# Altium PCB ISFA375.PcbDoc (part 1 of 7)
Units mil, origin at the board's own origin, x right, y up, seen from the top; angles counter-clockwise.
Board outline 5615 x 5520 mil, 6 copper layers (Top_SL, GND, POWER, Signal_Layer, GND2, Bottom_SL), stack 60.472 mil thick; 494 components, 307 nets, 1648 pads, 755 vias.
Unrouted connection lines stored in the file: 315.
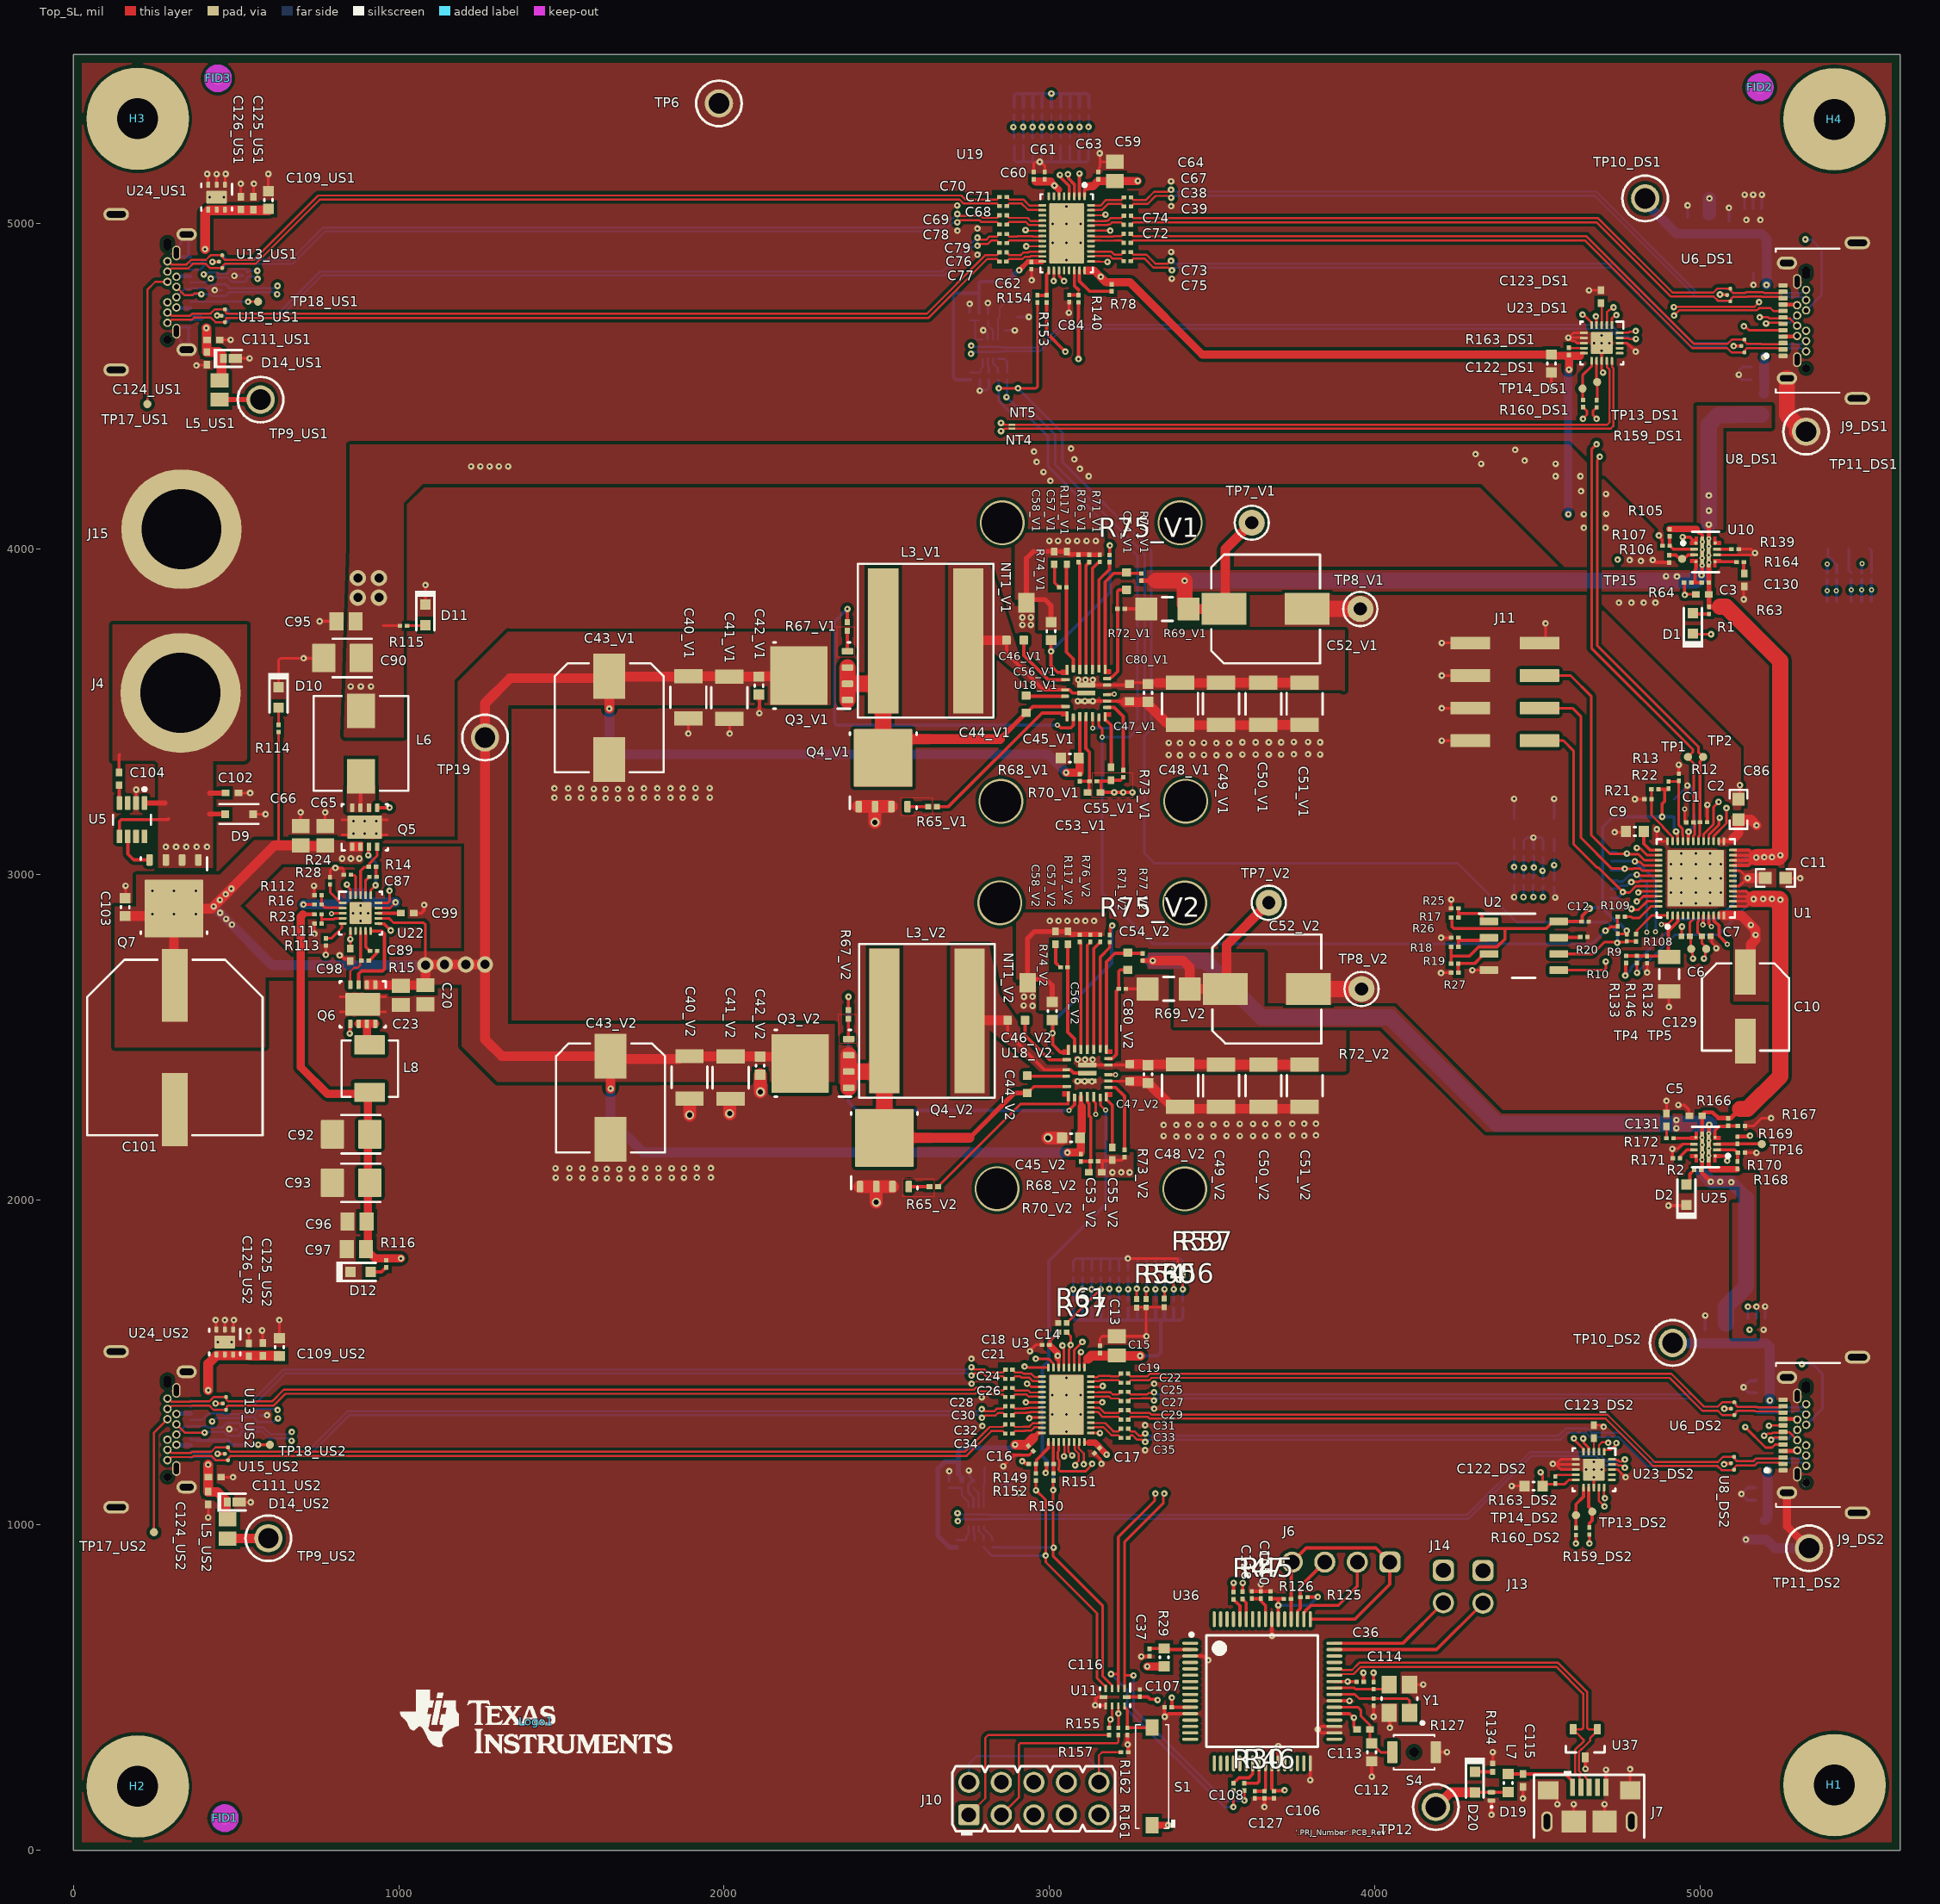
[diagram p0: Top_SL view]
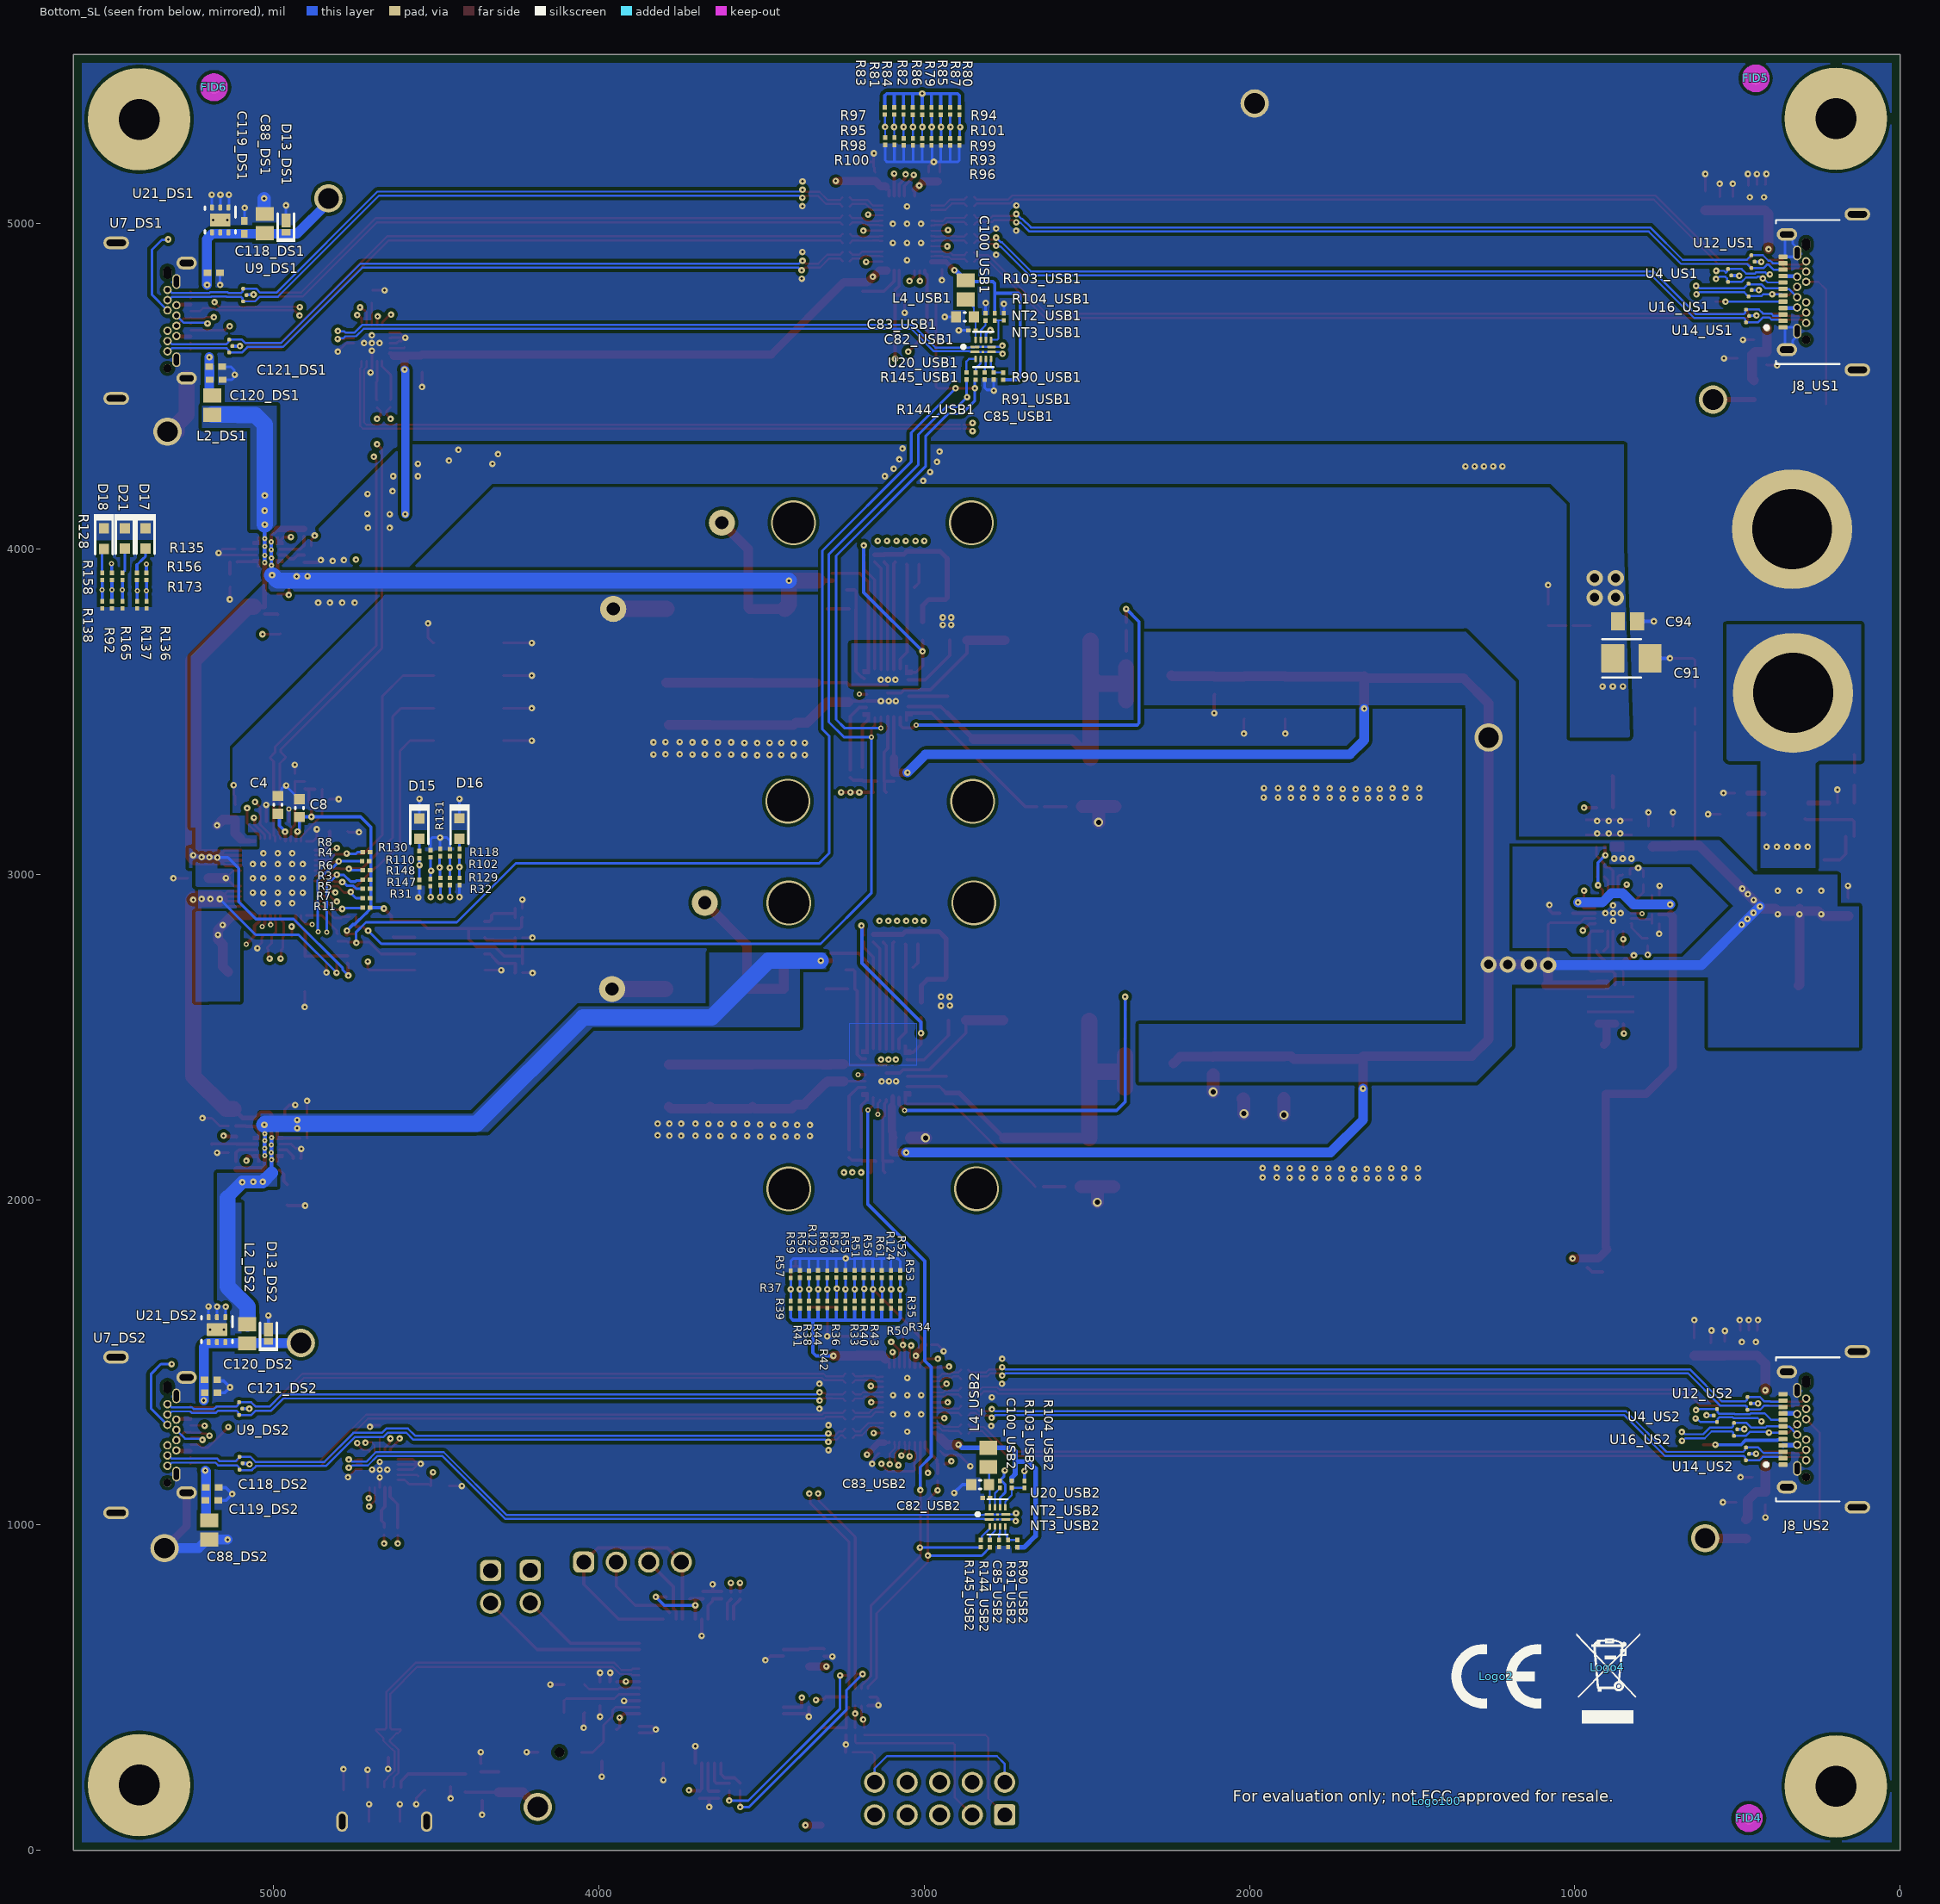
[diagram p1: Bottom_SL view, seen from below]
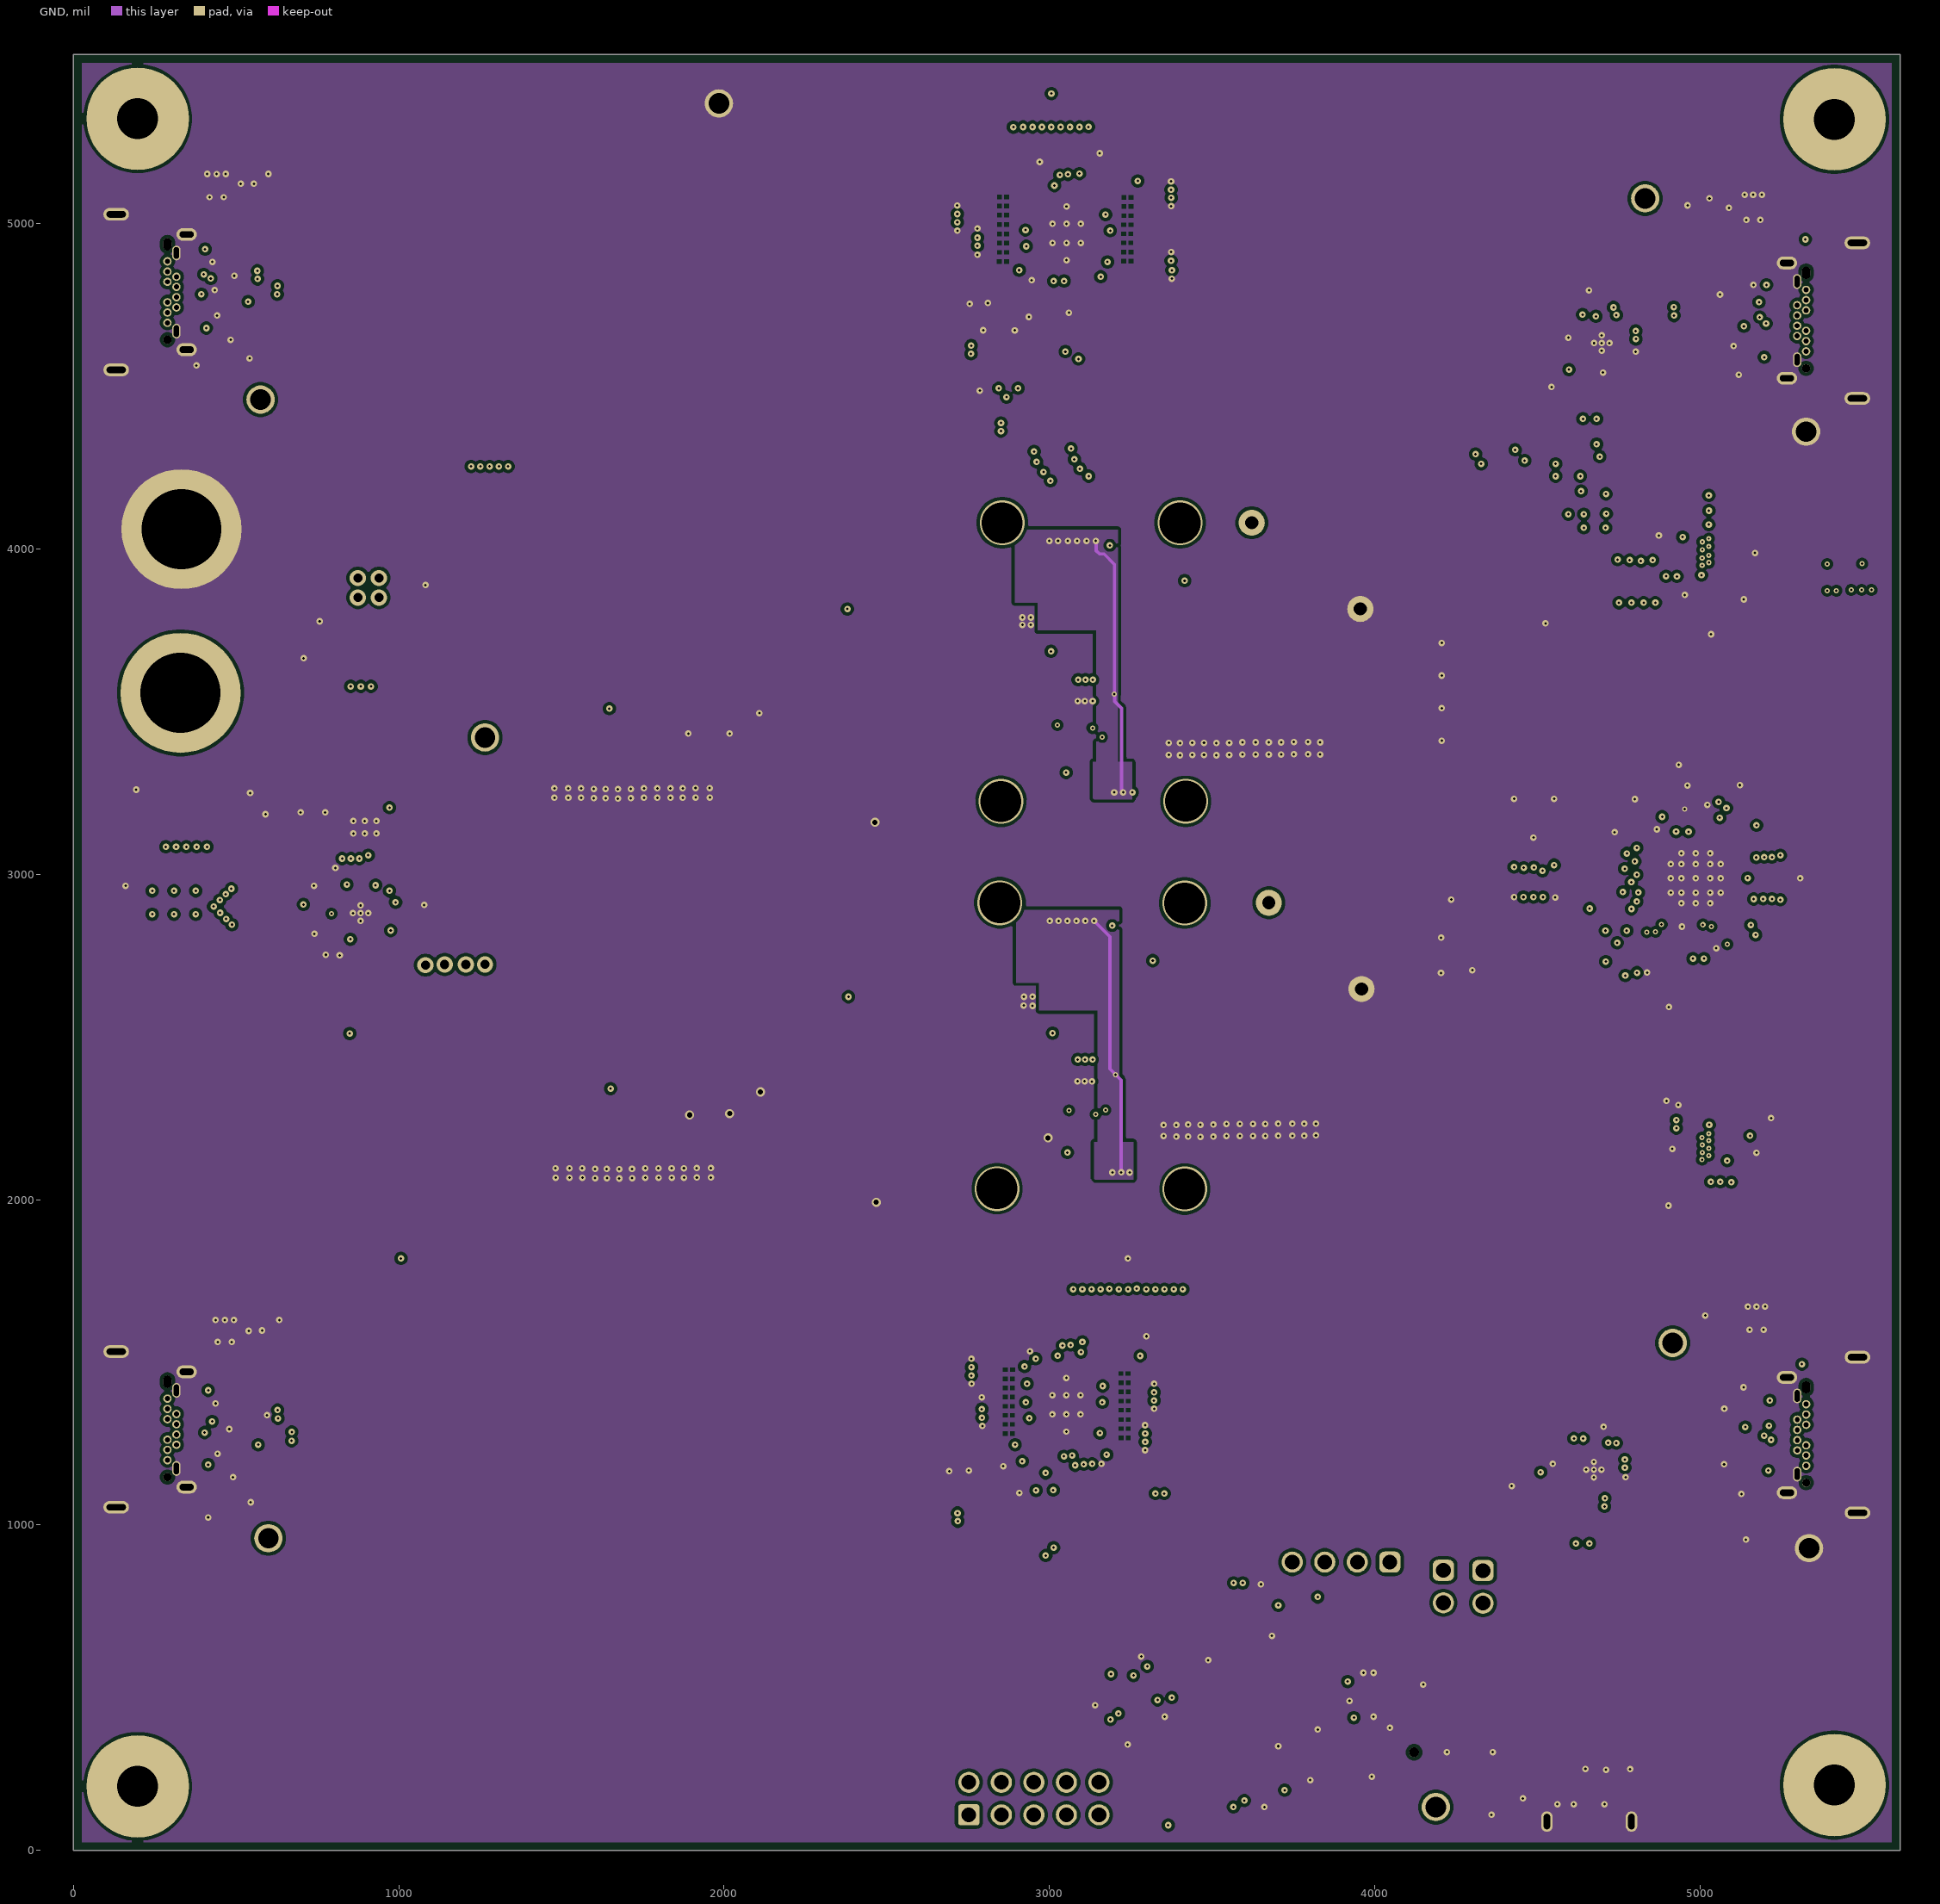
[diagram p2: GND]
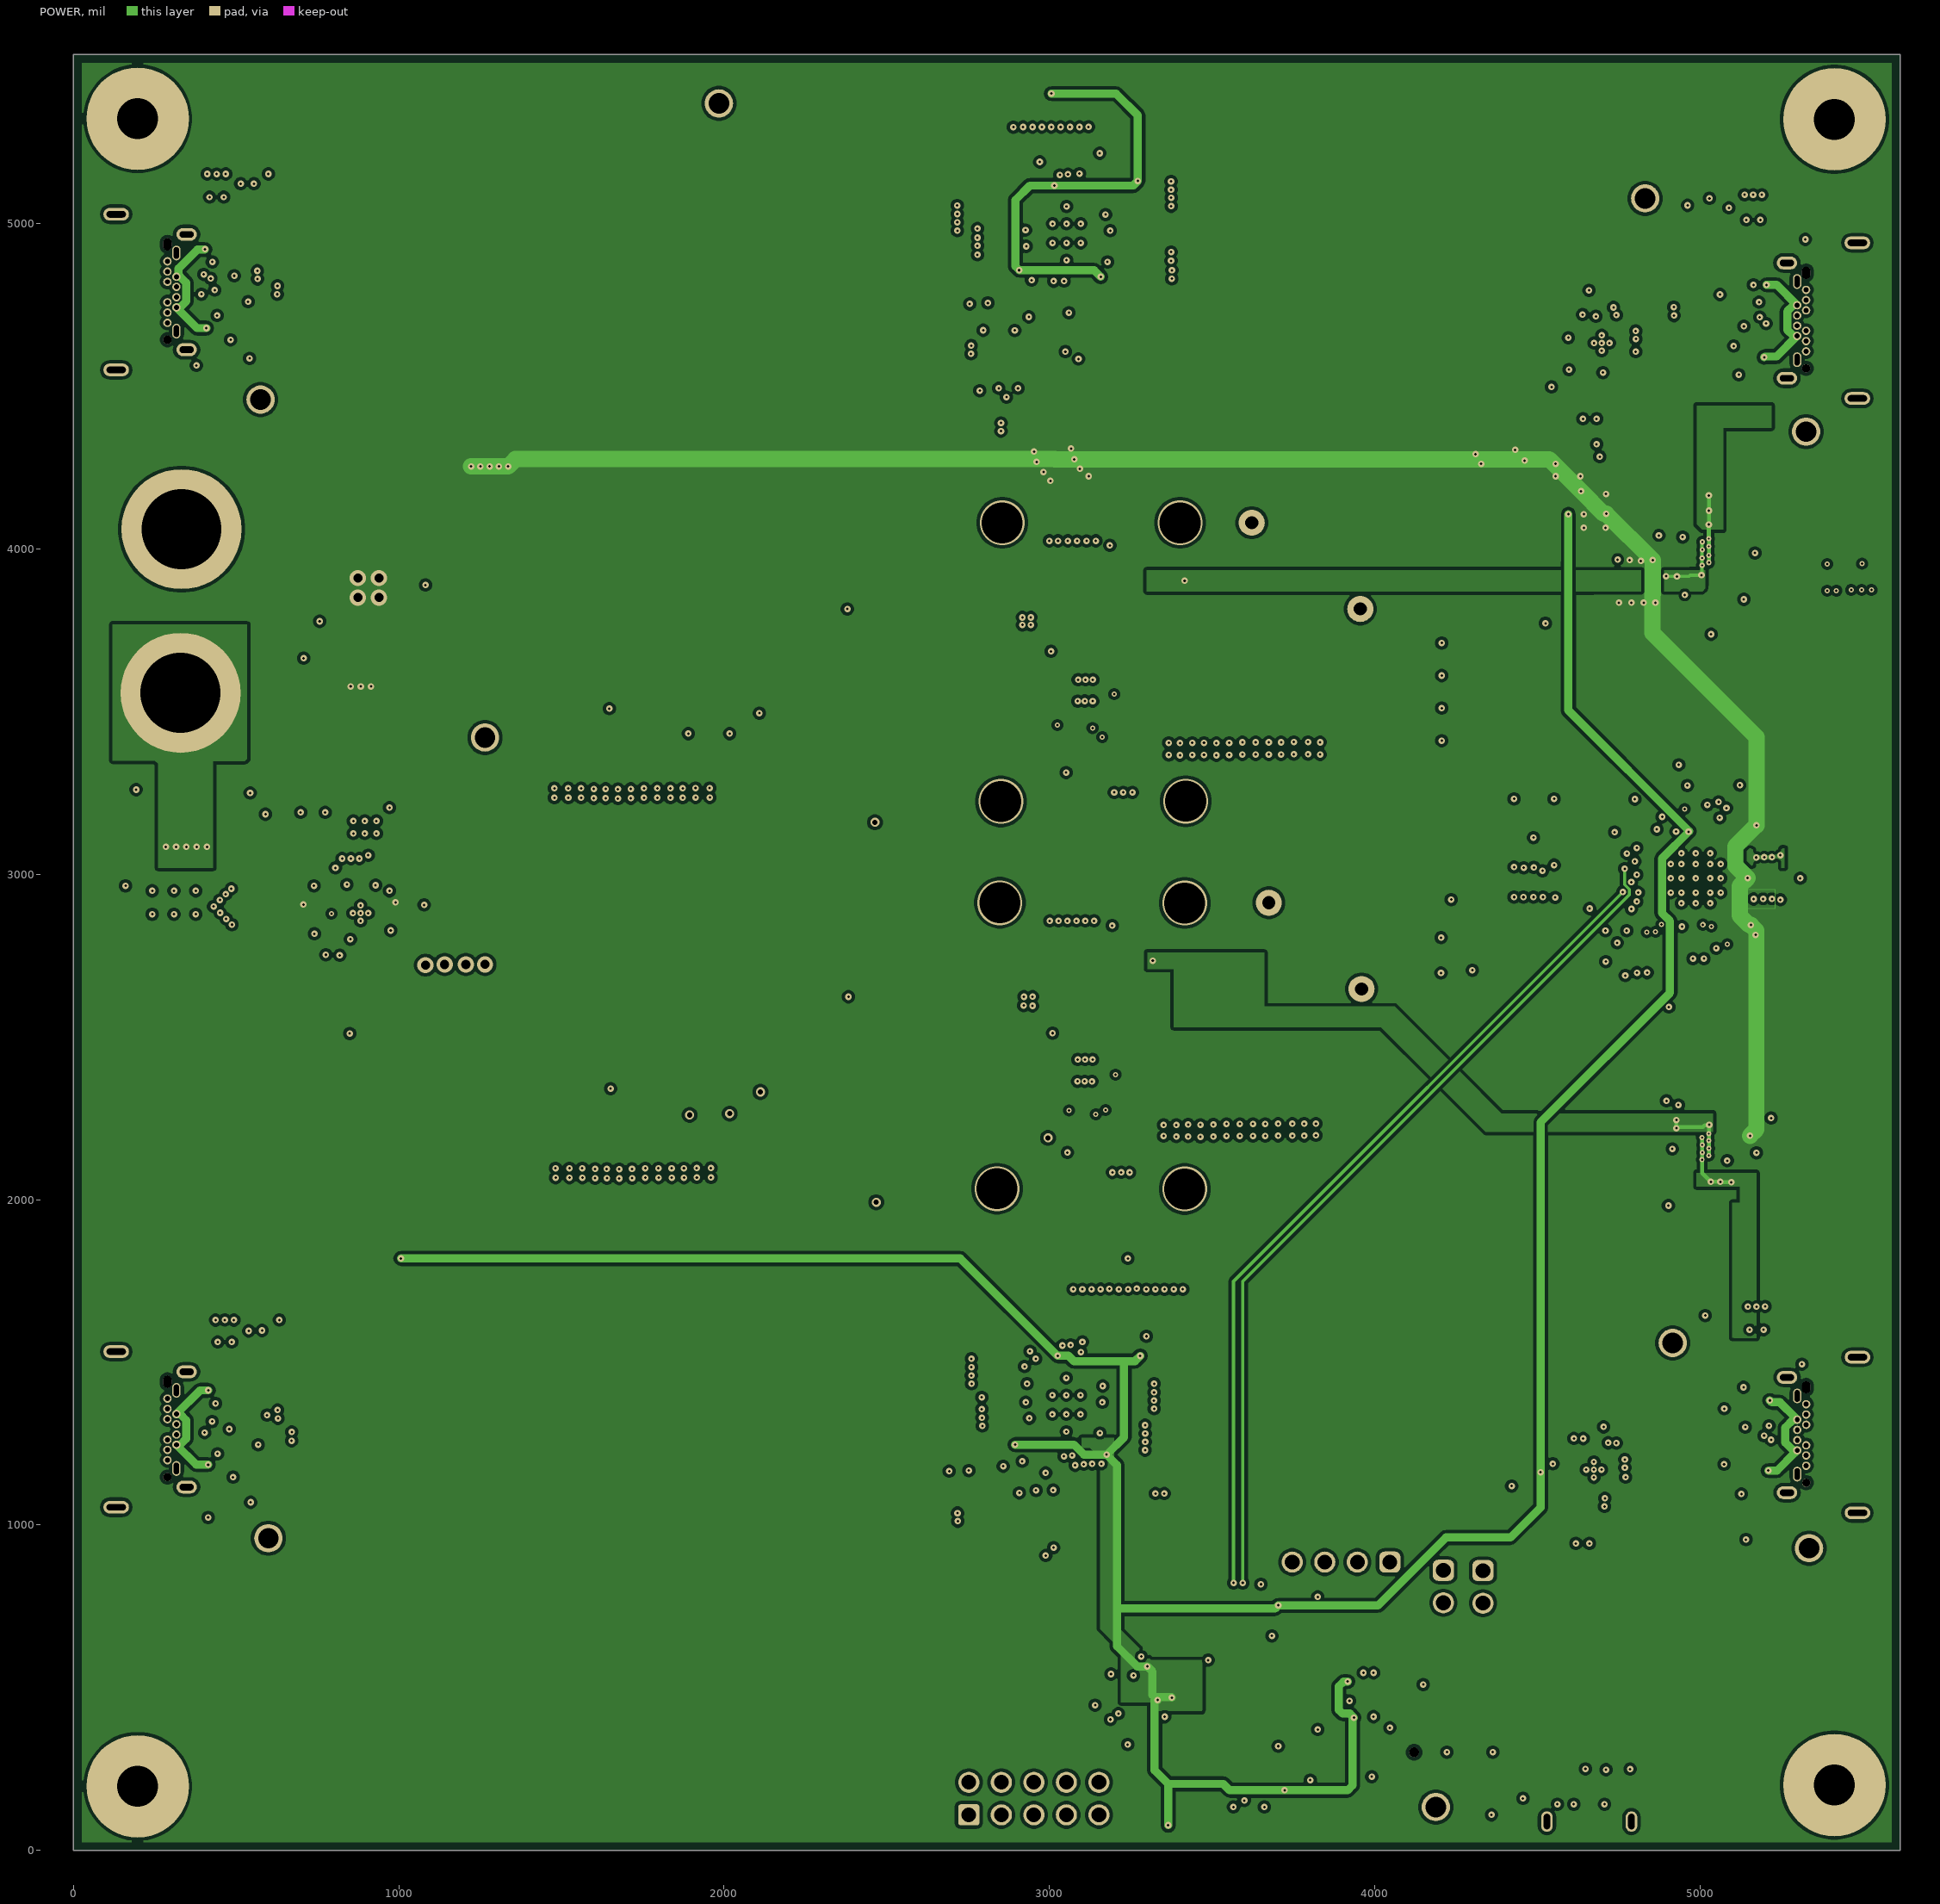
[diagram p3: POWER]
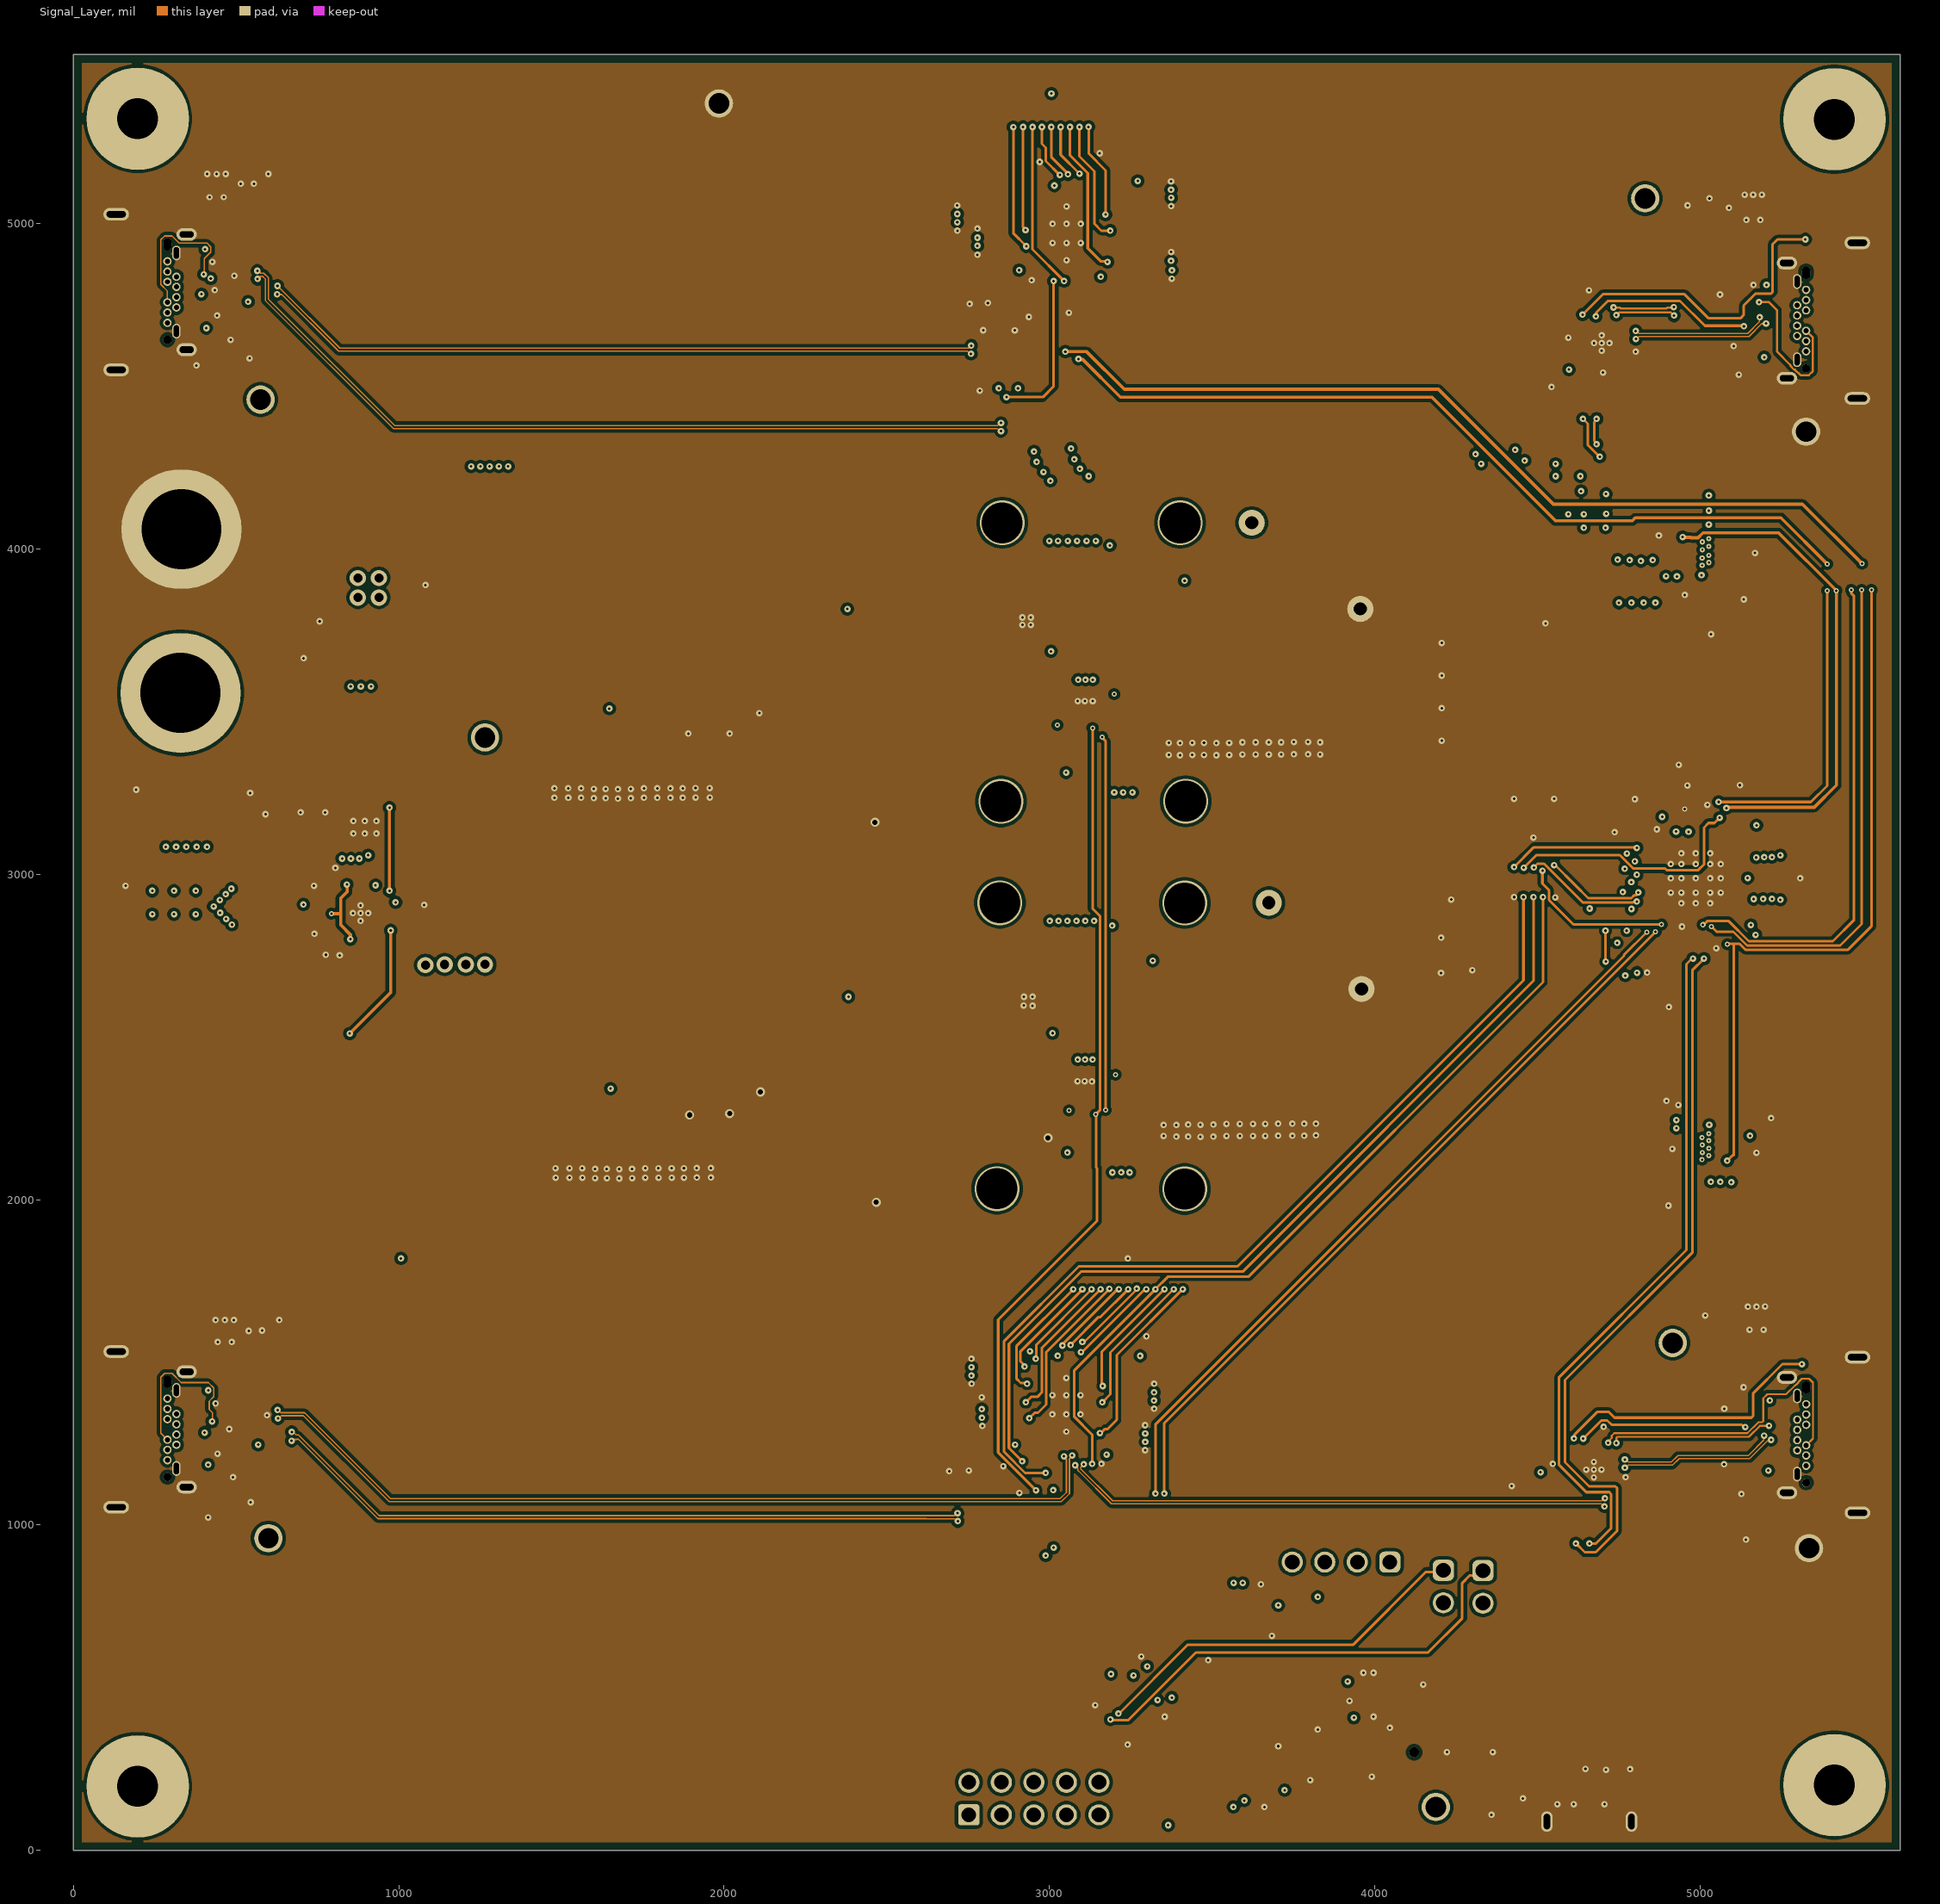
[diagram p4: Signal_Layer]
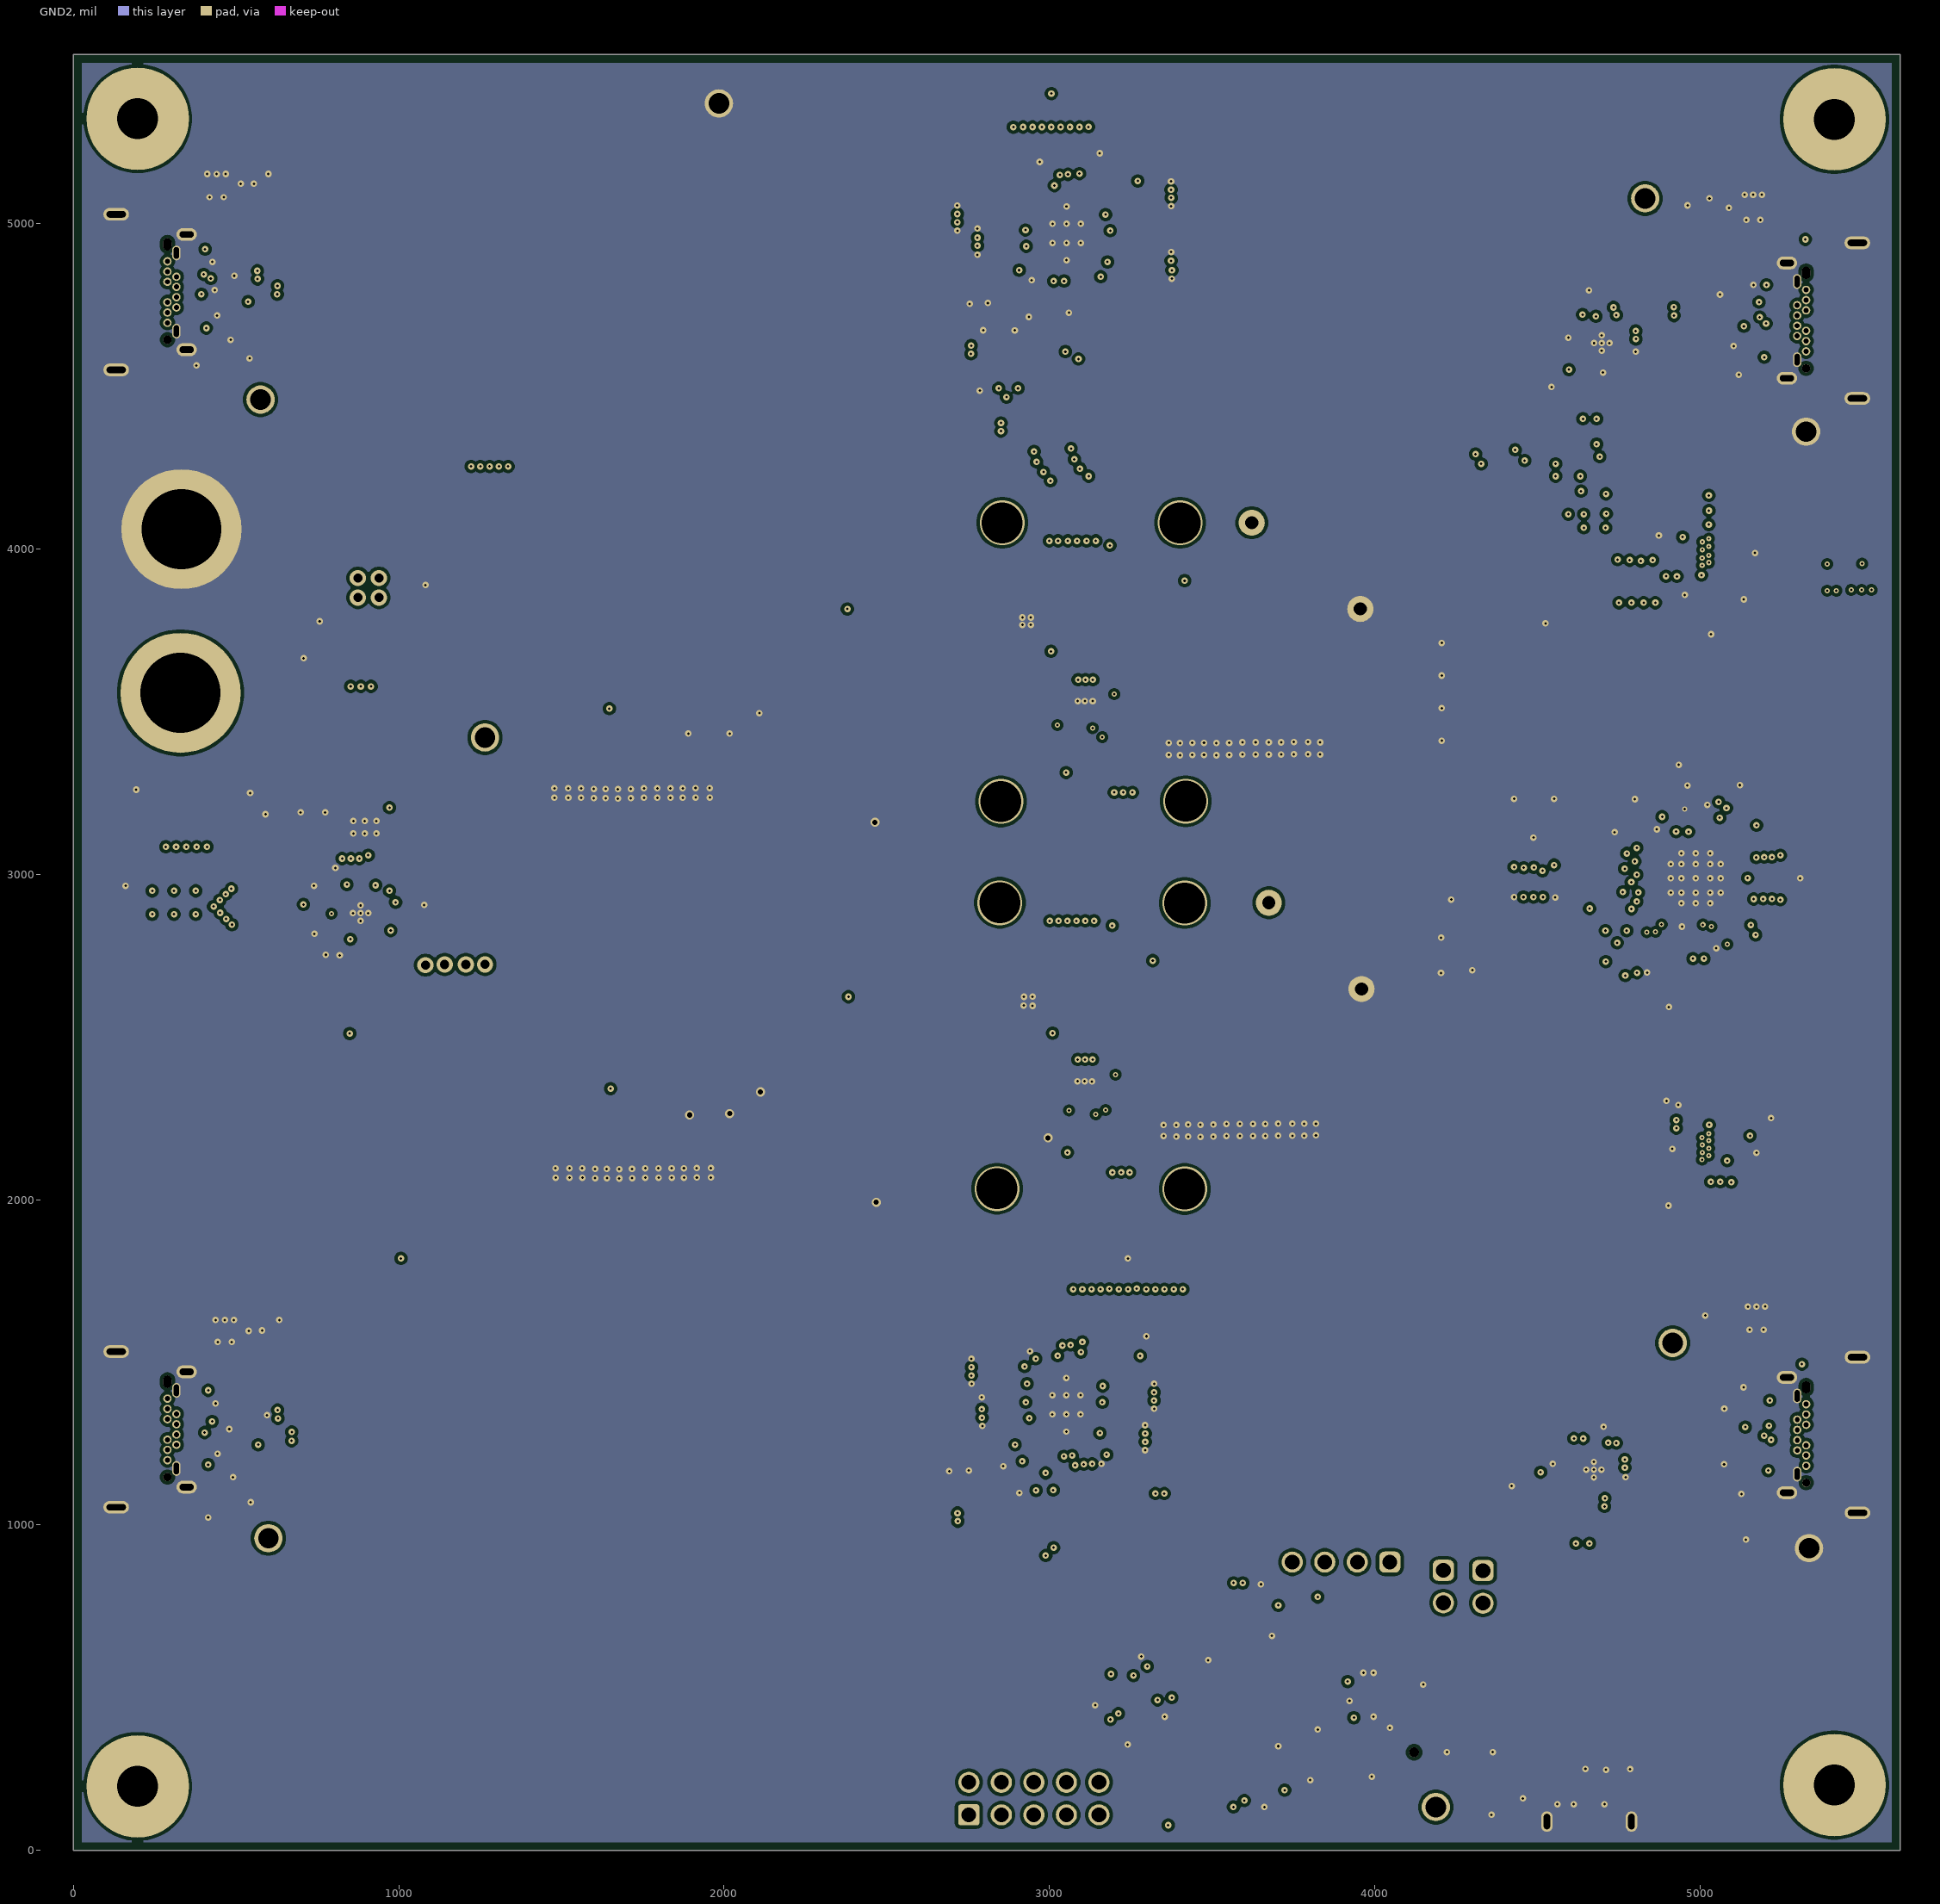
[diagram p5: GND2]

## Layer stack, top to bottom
Top Solder: solder mask 0.4, Solder Resist, Dk 3.5
Top_SL: signal copper 1.378
Dielectric 1: prepreg 5.669, FR-4, Dk 4.2
GND: signal copper 1.378
Dielectric 2: prepreg 16.929, FR-4, Dk 4.2
POWER: signal copper 1.378
Dielectric 3: core 7.008, FR-4, Dk 4.2
Signal_Layer: signal copper 1.378
Dielectric 4: prepreg 16.929, FR-4, Dk 4.2
GND2: signal copper 1.378
Dielectric 5: prepreg 5.669, FR-4, Dk 4.2
Bottom_SL: signal copper 1.378
Bottom Solder: solder mask 0.4, Solder Resist, Dk 3.5

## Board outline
0,0 5615,0 5615,5520 0,5520

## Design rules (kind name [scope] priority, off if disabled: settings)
AcuteAngle [All] p1: minimum=4.50000000000000E+0001 checktracksonly=FALSE
AssemblyTestPointUsage [All] p1: valid=2
BoardOutlineClearance BoardOutlineClearance_MountingHoles [OnCopper and InComponentClass('Mounting Holes')] p1: gap=39.37 ignorepadtopadclearanceinfootprint=FALSE
BoardOutlineClearance BoardOutlineClearance_Poly [OnCopper and IsPoly] p2: gap=25 ignorepadtopadclearanceinfootprint=FALSE
BoardOutlineClearance [OnCopper and Not InComponentClass('Logo') and not InComponentClass('FiducialMark') and not InRegion(1000,500,4000,800) and not InPoly] p3: gap=40 ignorepadtopadclearanceinfootprint=FALSE
Clearance Clearance_NetTie_1 [InNet('AUX_US1_*') vs InNet('AUX_DS1_*')] p1: gap=0 ignorepadtopadclearanceinfootprint=TRUE
Clearance Clearance_NetTie2 [InNet('D_US*') vs InNet('D1_D*')] p2: gap=0 ignorepadtopadclearanceinfootprint=TRUE
Clearance Clearance_Keepouts [((IsTrack Or IsArc) And Not InPoly) And IsFree and IsKeepOut vs ((IsTrack Or IsArc) And Not InPoly) And IsFree and IsKeepOut] p3: gap=0 ignorepadtopadclearanceinfootprint=FALSE
Clearance Clearance_Poly [InPolygon] p4: gap=10 ignorepadtopadclearanceinfootprint=TRUE
Clearance Clearance_FiducialMark [IsKeepOut and InComponentClass('FiducialMark') vs IsPad and InComponentClass('FiducialMark')] p5: gap=0 ignorepadtopadclearanceinfootprint=FALSE
Clearance [All] p6: gap=5 ignorepadtopadclearanceinfootprint=TRUE
ComponentClearance ComponentClearance_MountingHoles_FiducialMarks [InComponentClass('Mounting Holes') vs InComponentClass('FiducialMark')] p1: gap=50 collisioncheckmode=3 verticalgap=10 showdistances=FALSE
ComponentClearance ComponentClearance_Shunt [InComponentClass('Header') vs InComponentClass('Shunt')] p2: gap=0 collisioncheckmode=3 verticalgap=0 showdistances=FALSE
ComponentClearance ComponentClearance_Logo [InComponentClass('Logo')] p3: gap=30 collisioncheckmode=3 verticalgap=10 showdistances=FALSE
ComponentClearance ComponentClearance_ScrewToNut [(HasFootprint('NY PMS 440 0025 PH')) vs (HasFootprint('Keystone_1902C'))] p4: gap=5 collisioncheckmode=3 verticalgap=10 showdistances=FALSE
ComponentClearance ComponentClearance_MountingHoles [InComponentClass('Mounting Holes')] p5: gap=100 collisioncheckmode=3 verticalgap=100000 showdistances=FALSE
ComponentClearance ComponentClearance_NetTie [InComponent('NT*')] p6: gap=4 collisioncheckmode=3 verticalgap=0 showdistances=FALSE
ComponentClearance ComponentClearance_SmallPassives [HasFootprint('0201*') or HasFootprint('0402*') or HasFootprint('0508') or HasFootprint('0603*') or HasFootprint('0612') or HasFootprint('0805*') or HasFootprint('0815*') or HasFootprint('0830*') or HasFootprint('1206*') or HasFootprint('1210*') or HasFootprint('1808*') or HasFootprint('1812*') or HasFootprint('1825*') or HasFootprint('2010*') or HasFootprint('2220*') or HasFootprint('2225*') or HasFootprint('2512*') or HasFootprint('2728*') or HasFootprint('3518*') vs HasFootprint('0201*') or HasFootprint('0402*') or HasFootprint('0508') or HasFootprint('0603*') or HasFootprint('0612') or HasFootprint('0805*') or HasFootprint('0815*') or HasFootprint('0830*') or HasFootprint('1206*') or HasFootprint('1210*') or HasFootprint('1808*') or HasFootprint('1812*') or HasFootprint('1825*') or HasFootprint('2010*') or HasFootprint('2220*') or HasFootprint('2225*') or HasFootprint('2512*') or HasFootprint('2728*') or HasFootprint('3518*')] p7: gap=14.96 collisioncheckmode=3 verticalgap=10 showdistances=FALSE
ComponentClearance ComponentClearance_THtoSMT [IsThruComponent vs IsSMTComponent] p8: gap=30 collisioncheckmode=3 verticalgap=30 showdistances=FALSE
ComponentClearance ComponentClearance_THtoTH [IsThruComponent vs IsThruComponent] p9: gap=20 collisioncheckmode=3 verticalgap=30 showdistances=FALSE
ComponentClearance [All] p10: gap=20 collisioncheckmode=3 verticalgap=10 showdistances=FALSE
DiffPairsRouting DiffPairs_90Z [InNetClass('Diff_pairs')] p1: maxlimit=100 minlimit=5 mostfreqgap=5 toplayer_mingap=6 toplayer_maxgap=6 toplayer_prefgap=6 toplayer_minwidth=6.5 toplayer_maxwidth=6.5 toplayer_prefwidth=6.5 midlayer2_maxgap=5 midlayer2_minwidth=4.32 midlayer2_maxwidth=4.32 midlayer2_prefwidth=4.32 midlayer3_maxgap=5 midlayer3_minwidth=4.32 midlayer3_maxwidth=4.32 midlayer3_prefwidth=4.32 bottomlayer_mingap=6 bottomlayer_maxgap=6 bottomlayer_prefgap=6 bottomlayer_minwidth=6.5 bottomlayer_maxwidth=6.5 bottomlayer_prefwidth=6.5 impedanceprofiledriven=TRUE impedanceprofileid={51F6E1A3-C1B2-41CA-98E9-5ADEC133D8DC} impedanceprofilevalue=90.000000 maxuncoupledlength=1000
FabricationTestPointUsage TestPointUsage [All] p1: valid=2 allowmultiple=FALSE
FabricationTestpoint Testpoint [All] p1: side=3 testpointundercomponent=TRUE minsize=40 maxsize=100 preferedsize=60 minholesize=0 maxholesize=40 preferedholesize=32 testpointgrid=1 allowsidetop=TRUE allowsidebottom=TRUE usegrid=TRUE gridtolerance=0.01
FanoutControl Fanout_LCC [IsLCC] p1: bgadir=Out bgaviamode=Centered fanoutstyle=Auto fanoutdirection=Alternating viagrid=1 // Fanout_LCC (Default Rule)
FanoutControl Fanout_BGA [IsBGA] p2: bgadir=Out bgaviamode=Centered fanoutstyle=Auto fanoutdirection=Alternating viagrid=1 // Fanout_BGA (Default Rule)
FanoutControl Fanout_Default [All] p4: bgadir=Out bgaviamode=Centered fanoutstyle=Auto fanoutdirection=Alternating viagrid=1 // Fanout_Default (Default Rule)
FanoutControl Fanout_Small [(CompPinCount < 5)] p5: bgadir=Out bgaviamode=Centered fanoutstyle=Auto fanoutdirection=OutThenIn viagrid=1 // Fanout_Small (Default Rule)
HoleSize [All] p1: absolutevalues=TRUE maxlimit=251 minlimit=4 maxpercent=80.000 minpercent=20.000
HoleToHoleClearance [All] p1: gap=1 allowstackedmicrovias=TRUE
MinimumAnnularRing MinimumAnnularRing_ThermalPadVias [IsVia and InAnyComponent] p1: minimumring=3.94
MinimumAnnularRing [All] p2: minimumring=3.94
MinimumSolderMaskSliver MinimumSolderMaskSliver_Logo [InComponentClass('Logo') vs InComponentClass('Logo')] p1: minsoldermaskwidth=0.7
MinimumSolderMaskSliver [All] p2: minsoldermaskwidth=1
PlaneConnect [All] p1: planeconnectstyle=Relief reliefexpansion=10 reliefentries=4 reliefconductorwidth=10 reliefairgap=10
PolygonConnect [All] p1: connectstyle=Direct reliefconductorwidth=10 reliefentries=4 polygonreliefangle="90 Angle" airgapwidth=10
RoomDefinition DS1 [InComponentClass('DS1')] p1: confinementstyle=ConfineIn formatcopy=TRUE lockcomponents=FALSE outline 4507.83,5165 5647,5165 5647,4283.6 4507.83,4283.6
RoomDefinition US2 [InComponentClass('US2')] p2: confinementstyle=ConfineIn formatcopy=TRUE lockcomponents=FALSE outline 1010.1,872.35 -40,872.35 -40,1682.35 1010.1,1682.35
RoomDefinition US1 [InComponentClass('US1')] p3: confinementstyle=ConfineIn formatcopy=TRUE lockcomponents=FALSE outline 1010.1,4322.59 -40,4322.59 -40,5132.59 1010.1,5132.59
RoomDefinition USB2 [InComponentClass('USB2')] p4: confinementstyle=ConfineIn formatcopy=TRUE lockcomponents=FALSE outline 2881.87,1270.22 2881.87,864.2 2583.14,864.2 2583.14,1270.22
RoomDefinition V1 [InComponentClass('V1')] p5: confinementstyle=ConfineIn formatcopy=TRUE lockcomponents=FALSE outline 1434.13,4174.17 4016.44,4174.17 4016.44,3135.17 1434.13,3135.17
RoomDefinition V2 [InComponentClass('V2')] p6: confinementstyle=ConfineIn formatcopy=TRUE lockcomponents=FALSE outline 1437.91,3006.17 4020.23,3006.17 4020.23,1947 1437.91,1947
RoomDefinition USB1 [InComponentClass('USB1')] p7: confinementstyle=ConfineIn formatcopy=TRUE lockcomponents=FALSE outline 2951.5,4864.42 2951.5,4452.9 2627.14,4452.9 2627.14,4864.42
RoomDefinition DS2 [InComponentClass('DS2')] p8: confinementstyle=ConfineIn formatcopy=TRUE lockcomponents=FALSE outline 4413.93,1716 5660.62,1716 5660.62,844.66 4413.93,844.66
RoutingVias ThermalPadVias [IsVia and InAnyComponent] p1: holewidth=7.87 width=19.68 viastyle="Through Hole" minholewidth=4 minwidth=19.68 maxholewidth=12.99 maxwidth=23.62
RoutingVias [All] p2: holewidth=16 width=34 viastyle="Through Hole" minholewidth=4 minwidth=16 maxholewidth=40 maxwidth=65
SilkToBoardRegionClearance [Not ((IsComment or IsDesignator) And (Hide <> 'False')) and not InRegion(1000,500,4000,800)] p1:
SilkToSilkClearance SilkToSilkClearance_Pb-FreeLogo [(HasFootprint('Pb-Free_Overlay_Medium') OR HasFootprint('Pb-Free_Overlay_Small')) vs (HasFootprint('Pb-Free_Overlay_Medium') OR HasFootprint('Pb-Free_Overlay_Small'))] p1: silktosilkclearance=0
SilkToSilkClearance [All] p2: silktosilkclearance=0
SilkToSolderMaskClearance SilkToComponentPadClearance [(IsPad or IsFill or IsRegion) and InAnycomponent] p1: minsilkscreentomaskgap=2 clearancetoexposedcopper=TRUE
SilkToSolderMaskClearance "Silk to Solder Mask Opening" [All] p2: minsilkscreentomaskgap=2 clearancetoexposedcopper=FALSE
SolderMaskExpansion [All] p1: expansion=1.97 istentingtop=FALSE
UnRoutedNet [All] p1: checkbadconnections=TRUE
Width [All] p1: maxlimit=100 minlimit=6 preferedwidth=10 checkconnectedcopper=TRUE
Width vbus [InNetClass('vbus')] p2: maxlimit=100 minlimit=25 preferedwidth=30 checkconnectedcopper=TRUE
Width CC_GPIO [InNetClass('All Nets')] p3: maxlimit=100 minlimit=10 preferedwidth=15 checkconnectedcopper=TRUE
13 further rules are at their usual default settings.

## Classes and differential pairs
net class VCC_5V: VCC_5V
net class vbus: NetC47_V1_1 NetC47_V2_1 NetC109_US1_1 NetC109_US2_1 NetL5_US1_2 NetL5_US2_2 PA_PPHV PA_VBUS PB_PPHV PB_VBUS VBUS_DS1 VBUS_DS2
net class Diff_pairs: AUX_DS2_N AUX_DS2_P AUX_US1_N AUX_US1_P AUX_US2_N AUX_US2_P CRX1_N CRX1_P CRX2_N CRX2_P CTX1_N CTX1_P CTX2_N CTX2_P D1_D_N D1_D_P D1_D_USB2_N D1_D_USB2_P D1_RX1_N D1_RX1_P D1_RX2_N D1_RX2_P D1_TX1_N D1_TX1_P D1_TX2_N D1_TX2_P D2_RX1_N D2_RX1_P D2_RX2_N D2_RX2_P D2_TX1_N D2_TX1_P D2_TX2_N D2_TX2_P D_US1_N D_US1_P D_US2_N D_US2_P DRX1_N DRX1_P DRX2_N DRX2_P DTX1_N DTX1_P DTX2_N DTX2_P F_USB_D_N F_USB_D_P RX1_US1_N RX1_US1_P RX1_US2_N RX1_US2_P RX2_US1_N RX2_US1_P RX2_US2_N RX2_US2_P SSRX1_N SSRX1_P SSRX2_N SSRX2_P SSTX1_N SSTX1_P SSTX2_N SSTX2_P TX1_US1_N TX1_US1_P TX1_US2_N TX1_US2_P TX2_US1_N TX2_US1_P TX2_US2_N TX2_US2_P URX1_N URX1_P URX2_N URX2_P UTX1_N UTX1_P UTX2_N UTX2_P
channel class ISFA375_REDRIVER_TUSB216I: USB1 USB2
component class USB2: C82_USB2 C83_USB2 C85_USB2 C100_USB2 L4_USB2 NT2_USB2 NT3_USB2 R90_USB2 R91_USB2 R103_USB2 R104_USB2 R144_USB2 R145_USB2 U20_USB2
component class USB1: C82_USB1 C83_USB1 C85_USB1 C100_USB1 L4_USB1 NT2_USB1 NT3_USB1 R90_USB1 R91_USB1 R103_USB1 R104_USB1 R144_USB1 R145_USB1 U20_USB1
component class V2: C40_V2 C41_V2 C42_V2 C43_V2 C44_V2 C45_V2 C46_V2 C47_V2 C48_V2 C49_V2 C50_V2 C51_V2 C52_V2 C53_V2 C54_V2 C55_V2 C56_V2 C57_V2 C58_V2 C80_V2 L3_V2 NT1_V2 Q3_V2 Q4_V2 R65_V2 R67_V2 R68_V2 R69_V2 R70_V2 R71_V2 R72_V2 R73_V2 R74_V2 R75_V2 R76_V2 R77_V2 R117_V2 TP7_V2 TP8_V2 U18_V2
component class V1: C40_V1 C41_V1 C42_V1 C43_V1 C44_V1 C45_V1 C46_V1 C47_V1 C48_V1 C49_V1 C50_V1 C51_V1 C52_V1 C53_V1 C54_V1 C55_V1 C56_V1 C57_V1 C58_V1 C80_V1 L3_V1 NT1_V1 Q3_V1 Q4_V1 R65_V1 R67_V1 R68_V1 R69_V1 R70_V1 R71_V1 R72_V1 R73_V1 R74_V1 R75_V1 R76_V1 R77_V1 R117_V1 TP7_V1 TP8_V1 U18_V1
component class US1: C109_US1 C111_US1 C124_US1 C125_US1 C126_US1 D14_US1 J8_US1 L5_US1 TP9_US1 TP17_US1 TP18_US1 U4_US1 U12_US1 U13_US1 U14_US1 U15_US1 U16_US1 U24_US1
component class DS2: C88_DS2 C118_DS2 C119_DS2 C120_DS2 C121_DS2 C122_DS2 C123_DS2 D13_DS2 J9_DS2 L2_DS2 R159_DS2 R160_DS2 R163_DS2 TP10_DS2 TP11_DS2 TP13_DS2 TP14_DS2 U6_DS2 U7_DS2 U8_DS2 U9_DS2 U21_DS2 U23_DS2
channel class ISFA375_US_USB-C_CONN: US1 US2 US-1 US-2
component class "Sideband Interface": .Layer_Name J11
component class "Mounting Holes": .Layer_Name H1 H2 H3 H4
component class Logo: .Layer_Name Logo1
component class Hardware: !PCB .Layer_Name FID1 FID2 FID3 FID4 FID5 FID6 H1 H2 H3 H4 Logo1 Logo2 Logo4 Logo100
component class FiducialMark: .Layer_Name FID1 FID2 FID3 FID4 FID5 FID6
channel class ISFA375_DS_USB-C_CONN: DS1 DS2
channel class ISFA375_BUS_POWER_TPS55288: V1 V2 VBUS1 VBUS2
component class "TUSB1104 Redriver": .Layer_Name C38 C39 C59 C60 C61 C62 C63 C64 C67 C68 C69 C70 C71 C72 C73 C74 C75 C76 C77 C78 C79 C84 NT4 NT5 R78 R79 R80 R81 R82 R83 R84 R85 R86 R87 R93 R94 R95 R96 R97 R98 R99 R100 R101 R140 R153 R154 U19
component class "TUSB1044 Redriver": .Layer_Name C13 C14 C15 C16 C17 C18 C19 C21 C22 C24 C25 C26 C27 C28 C29 C30 C31 C32 C33 C34 C35 R33 R34 R35 R36 R37 R38 R39 R40 R41 R42 R43 R44 R50 R51 R52 R53 R54 R55 R56 R57 R58 R59 R60 R61 R123 R124 R149 R150 R151 R152 U3
component class "TPS65994 PD Controller": .Layer_Name C1 C2 C3 C4 C5 C6 C7 C8 C9 C10 C11 C12 C86 C129 C130 C131 D1 D2 D15 D16 D17 D18 D21 R1 R2 R3 R4 R5 R6 R7 R8 R9 R10 R11 R12 R13 R17 R18 R19 R20 R21 R22 R25 R26 R27 R31 R32 R63 R64 R92 R102 R105 R106 R107 R108 R109 R110 R118 R128 R129 R130 R131 R132 R133 R135 R136 R137 R138 R139 R146 R147 R148 R156 R158 R164 R165 R166 R167 R168 R169 R170 R171 R172 R173 TP1 TP2 TP4 TP5 TP15 TP16 U1 U2 U10 U25
component class US2: .Layer_Name C109_US2 C111_US2 C124_US2 C125_US2 C126_US2 D14_US2 J8_US2 L5_US2 TP9_US2 TP17_US2 TP18_US2 U4_US2 U12_US2 U13_US2 U14_US2 U15_US2 U16_US2 U24_US2
component class DS1: .Layer_Name C88_DS1 C118_DS1 C119_DS1 C120_DS1 C121_DS1 C122_DS1 C123_DS1 D13_DS1 J9_DS1 L2_DS1 R159_DS1 R160_DS1 R163_DS1 TP10_DS1 TP11_DS1 TP13_DS1 TP14_DS1 U6_DS1 U7_DS1 U8_DS1 U9_DS1 U21_DS1 U23_DS1
component class "MCU Debug Interface": .Layer_Name C36 C37 C105 C106 C107 C108 C110 C112 C113 C114 C115 C116 C127 C128 D19 D20 J6 J7 J10 J13 J14 L7 R29 R30 R45 R46 R47 R125 R126 R127 R134 R155 R157 R161 R162 S1 S4 TP12 U11 U36 U37 Y1
component class "Input Power Supply": .Layer_Name C20 C23 C65 C66 C87 C89 C90 C91 C92 C93 C94 C95 C96 C97 C98 C99 C101 C102 C103 C104 D9 D10 D11 D12 J4 J15 L6 L8 Q5 Q6 Q7 R14 R15 R16 R23 R24 R28 R111 R112 R113 R114 R115 R116 TP6 TP19 U5 U22
component class Header: .Layer_Name J6 J10 J11 J13 J14
differential pair F_USB_D: +F_USB_D_P -F_USB_D_N
differential pair D_US2: +D_US2_P -D_US2_N
differential pair D_US1: +D_US1_P -D_US1_N
differential pair UTX2: +UTX2_P -UTX2_N
differential pair UTX1: +UTX1_P -UTX1_N
differential pair URX2: +URX2_P -URX2_N
differential pair URX1: +URX1_P -URX1_N
differential pair SSTX2: +SSTX2_P -SSTX2_N
differential pair SSTX1: +SSTX1_P -SSTX1_N
differential pair SSRX2: +SSRX2_P -SSRX2_N
differential pair SSRX1: +SSRX1_P -SSRX1_N
differential pair DTX2: +DTX2_P -DTX2_N
differential pair DTX1: +DTX1_P -DTX1_N
differential pair DRX2: +DRX2_P -DRX2_N
differential pair DRX1: +DRX1_P -DRX1_N
differential pair CTX2: +CTX2_P -CTX2_N
differential pair CTX1: +CTX1_P -CTX1_N
differential pair CRX2: +CRX2_P -CRX2_N
differential pair CRX1: +CRX1_P -CRX1_N
differential pair D1_D_USB2: +D1_D_USB2_P -D1_D_USB2_N
differential pair TX2_US2: +TX2_US2_P -TX2_US2_N
differential pair TX2_US1: +TX2_US1_P -TX2_US1_N
differential pair TX1_US2: +TX1_US2_P -TX1_US2_N
differential pair TX1_US1: +TX1_US1_P -TX1_US1_N
differential pair RX2_US2: +RX2_US2_P -RX2_US2_N
differential pair RX2_US1: +RX2_US1_P -RX2_US1_N
differential pair RX1_US2: +RX1_US2_P -RX1_US2_N
differential pair RX1_US1: +RX1_US1_P -RX1_US1_N
differential pair C_AUX_DS2: +C_AUX_DS2_P -C_AUX_DS2_N
differential pair AUX_US1: +AUX_US1_P -AUX_US1_N
differential pair AUX_DS2: +AUX_DS2_P -AUX_DS2_N
differential pair C_AUX_DS1: +C_AUX_DS1_P -C_AUX_DS1_N
differential pair D2_TX1: +D2_TX1_P -D2_TX1_N
differential pair D1_TX1: +D1_TX1_P -D1_TX1_N
differential pair AUX_US2: +AUX_US2_P -AUX_US2_N
differential pair AUX_DS1: +AUX_DS1_P -AUX_DS1_N
differential pair D1_D: +D1_D_P -D1_D_N
differential pair D2_RX2: +D2_RX2_P -D2_RX2_N
differential pair D2_TX2: +D2_TX2_P -D2_TX2_N
differential pair D2_RX1: +D2_RX1_P -D2_RX1_N
differential pair D1_TX2: +D1_TX2_P -D1_TX2_N
differential pair D1_RX2: +D1_RX2_P -D1_RX2_N
differential pair D1_RX1: +D1_RX1_P -D1_RX1_N

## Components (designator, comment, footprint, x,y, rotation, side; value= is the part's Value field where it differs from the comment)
C1 "CGA1A2X7R1H221K030BA" 0201_033L 4969,3160 r0 top value=220pF
C2 "CGA1A2X7R1H221K030BA" 0201_033L 5010.89,3160.63 r180 top value=220pF
C3 "GRM155R6YA105KE11D" 0402L 5007.54,3861 r180 top value=1uF
C4 "GRM188R61E106MA73D" 0603L 4987,3213.78 r90 bottom value=10uF
C5 "GRM155R6YA105KE11D" 0402L 4986.77,2258.13 r180 top value=1uF
C6 "CGA1A2X7R1H221K030BA" 0201_033 4956.01,2810 r180 top value=220pF
C7 "CGA1A2X7R1H221K030BA" 0201_033 5019,2810 r0 top value=220pF
C8 "GRM188R61E106MA73D" 0603L 4920.5,3204 r270 bottom value=10uF
C9 "GRM188R61E106MA73D" 0603L 4799.9,3132.03 r0 top value=10uF
C10 "APXE100ARA121MF61G" CAPSMT_62_F61 5138.69,2594.59 r270 top value=120uF
C11 "GRM188R61E106MA73D" 0603 5231.86,2988.87 r0 top value=10uF
C12 "GRM033C71C104KE14D" 0201_033L 4646.9,2855.09 r0 top value=0.1uF
C13 "CL21B106KOQNNNE" 0805L 3207.1,1550.69 r90 top value=10uF
C14 "GRM033R61A104KE84D" 0201_033L 2988.72,1553.84 r180 top value=0.1uF
C15 "GRM033R61A104KE84D" 0201_033L 3155.61,1539.67 r90 top value=0.1uF
C16 "GRM033R61A104KE84D" 0201_033L 2943,1235.43 r315 top value=0.1uF
C17 "GRM033R61A104KE84D" 0201_033L 3146.65,1229.08 r225 top value=0.1uF
C18 "C0603X5R1A334K030BC" 0201_033L 2875.65,1477.42 r180 top value=0.33uF
C19 "C0603X5R1A334K030BC" 0201_033L 3230.72,1465.61 r180 top value=0.33uF
C20 "C2012X5R1V226M125AC" 0805L 1081.61,2630.03 r270 top value=22uF
C21 "C0603X5R1A334K030BC" 0201_033L 2875.37,1449.36 r180 top value=0.33uF
C22 "C0603X5R1A334K030BC" 0201_033L 3231.09,1437.29 r180 top value=0.33uF
C23 "C2012X5R1V226M125AC" 0805L 1006.61,2628.03 r270 top value=22uF
C24 "LMK063BJ224MP-F" 0201_033L 2875.37,1421.36 r180 top value=0.22uF
C25 "LMK063BJ224MP-F" 0201_033L 3231.09,1409.29 r180 top value=0.22uF
C26 "LMK063BJ224MP-F" 0201_033L 2875.37,1393.36 r180 top value=0.22uF
C27 "LMK063BJ224MP-F" 0201_033L 3231.09,1381.29 r180 top value=0.22uF
C28 "LMK063BJ224MP-F" 0201_033L 2875.37,1365.36 r180 top value=0.22uF
C29 "LMK063BJ224MP-F" 0201_033L 3231.09,1353.29 r180 top value=0.22uF
C30 "LMK063BJ224MP-F" 0201_033L 2875.37,1337.36 r180 top value=0.22uF
C31 "LMK063BJ224MP-F" 0201_033L 3231.09,1324.29 r180 top value=0.22uF
C32 "C0603X5R1A334K030BC" 0201_033L 2875.37,1309.36 r180 top value=0.33uF
C33 "C0603X5R1A334K030BC" 0201_033L 3231.09,1296.29 r180 top value=0.33uF
C34 "C0603X5R1A334K030BC" 0201_033L 2875.37,1281.36 r180 top value=0.33uF
C35 "C0603X5R1A334K030BC" 0201_033L 3231.09,1267.69 r180 top value=0.33uF
C36 "GRM033Z71C104KE14D" 0201L 3955.42,518.32 r0 top value=0.1uF
C37 "GRM033Z71C104KE14D" 0201L 3307.64,608.17 r90 top value=0.1uF
C38 "C0603X5R1A334K030BC" 0201_033L 3239.94,5024.96 r180 top value=0.33uF
C39 "C0603X5R1A334K030BC" 0201_033L 3239.52,4996.92 r180 top value=0.33uF
C40_V1 "CGA6P1X7R1N106M250AC" 1210_280 1890.13,3544.17 r270 top value=10uF (schematic designator C40)
C40_V2 "CGA6P1X7R1N106M250AC" 1210_280 1893.91,2376.17 r270 top value=10uF (schematic designator C40)
C41_V1 "CGA6P1X7R1N106M250AC" 1210_280 2016.13,3543.17 r270 top value=10uF (schematic designator C41)
C41_V2 "CGA6P1X7R1N106M250AC" 1210_280 2019.91,2375.17 r270 top value=10uF (schematic designator C41)
C42_V1 "GRT188R61H105ME13D" 0603L 2107.13,3580.17 r270 top value=1uF (schematic designator C42)
C42_V2 "GRT188R61H105ME13D" 0603L 2110.91,2412.17 r270 top value=1uF (schematic designator C42)
C43_V1 "EEHZA1H680P" SM_RADIAL_8MM 1647.13,3481.17 r270 top value=68uF (schematic designator C43)
C43_V2 "EEHZA1H680P" SM_RADIAL_8MM 1650.91,2313.17 r270 top value=68uF (schematic designator C43)
C44_V1 "GCM188L81H104KA57D" FP-GCM188L81H104KA57D_0603-MFG 2928.2,3522.91 r270 top (schematic designator C44)
C44_V2 "GCM188L81H104KA57D" FP-GCM188L81H104KA57D_0603-MFG 2931.99,2354.91 r270 top (schematic designator C44)
C45_V1 "GRT188R61H105ME13D" 0603L 3062.6,3358.01 r180 top value=1uF (schematic designator C45)
C45_V2 "GRT188R61H105ME13D" 0603L 3066.39,2190.01 r180 top value=1uF (schematic designator C45)
C46_V1 "GCM188L81H104KA57D" FP-GCM188L81H104KA57D_0603-MFG 2894.74,3719.88 r180 top (schematic designator C46)
C46_V2 "GCM188L81H104KA57D" FP-GCM188L81H104KA57D_0603-MFG 2898.53,2551.88 r180 top (schematic designator C46)
C47_V1 "GRT188R61H105ME13D" 0603L 3303.15,3557.73 r270 top value=1uF (schematic designator C47)
C47_V2 "GRT188R61H105ME13D" 0603L 3303,2386 r270 top value=1uF (schematic designator C47)
C48_V1 "CGA6P1X7R1N106M250AC" 1210_280 3401.58,3524.63 r270 top value=10uF (schematic designator C48)
C48_V2 "CGA6P1X7R1N106M250AC" 1210_280 3401.64,2351.01 r270 top value=10uF (schematic designator C48)
C49_V1 "CGA6P1X7R1N106M250AC" 1210_280 3527.59,3524.36 r270 top value=10uF (schematic designator C49)
C49_V2 "CGA6P1X7R1N106M250AC" 1210_280 3527.65,2350.73 r270 top value=10uF (schematic designator C49)
C50_V1 "CGA6P1X7R1N106M250AC" 1210_280 3657.47,3524.25 r270 top value=10uF (schematic designator C50)
C50_V2 "CGA6P1X7R1N106M250AC" 1210_280 3657.53,2350.63 r270 top value=10uF (schematic designator C50)
C51_V1 "CGA6P1X7R1N106M250AC" 1210_280 3784.47,3524.25 r270 top value=10uF (schematic designator C51)
C51_V2 "CGA6P1X7R1N106M250AC" 1210_280 3784.53,2350.63 r270 top value=10uF (schematic designator C51)
C52_V1 "EEHZA1E221P" SM_RADIAL_8MM 3664.74,3815.9 r0 top value=220uF (schematic designator C52)
C52_V2 "EEHZA1E221P" SM_RADIAL_8MM 3668.53,2647.9 r0 top value=220uF (schematic designator C52)
C53_V1 "CGA2B3X7R1H104K050BB" 0402L 3137.13,3252.17 r0 top value=0.1uF (schematic designator C53)
C53_V2 "CGA2B3X7R1H104K050BB" 0402L 3140.91,2084.17 r0 top value=0.1uF (schematic designator C53)
C54_V1 "GCM188L81H104KA57D" FP-GCM188L81H104KA57D_0603-MFG 3237.29,3901.32 r90 top (schematic designator C54)
C54_V2 "GCM188L81H104KA57D" FP-GCM188L81H104KA57D_0603-MFG 3241.08,2733.32 r90 top (schematic designator C54)
C55_V1 "CGA2B3X7R1H103K050BB" 0402L 3189.63,3309.39 r90 top value=0.01uF (schematic designator C55)
C55_V2 "CGA2B3X7R1H103K050BB" 0402L 3193.42,2141.39 r90 top value=0.01uF (schematic designator C55)
C56_V1 "GRT188R61C475KE13D" 0603L 3004.92,3748 r90 top value=4.7uF (schematic designator C56)
C56_V2 "GRT188R61C475KE13D" 0603L 3008.71,2580 r90 top value=4.7uF (schematic designator C56)
C57_V1 "CGA2B2C0G1H101J050BA" 0402L 3053.74,3972.88 r90 top value=100pF (schematic designator C57)
C57_V2 "CGA2B2C0G1H101J050BA" 0402L 3057.53,2804.88 r90 top value=100pF (schematic designator C57)
C58_V1 "CGA2B2X7R1H472K050BA" 0402L 3014.74,3972.88 r90 top value=4700pF (schematic designator C58)
C58_V2 "CGA2B2X7R1H472K050BA" 0402L 3018.53,2804.88 r90 top value=4700pF (schematic designator C58)
C59 "CL21B106KOQNNNE" 0805L 3201.31,5161 r90 top value=10uF
C60 "GRM033R61A104KE84D" 0201_033L 2951.5,5147.69 r90 top value=0.1uF
C61 "GRM033R61A104KE84D" 0201_033L 2985.63,5147.69 r90 top value=0.1uF
C62 "GRM033R61A104KE84D" 0201_033L 2944.65,4871.7 r270 top value=0.1uF
C63 "GRM033R61A104KE84D" 0201_033L 3150.01,5147.69 r90 top value=0.1uF
C64 "LMK063BJ224MP-F" 0201_033L 3239.94,5080.96 r180 top value=0.22uF
C65 "C2012X5R1V226M125AC" 0805L 773.75,3118.82 r90 top value=22uF
C66 "C2012X5R1V226M125AC" 0805L 698.61,3118.82 r90 top value=22uF
C67 "LMK063BJ224MP-F" 0201_033L 3239.94,5052.96 r180 top value=0.22uF
C68 "C0603X5R1A334K030BC" 0201_033L 2857.61,5026.34 r180 top value=0.33uF
C69 "C0603X5R1A334K030BC" 0201_033L 2857.61,4997.34 r180 top value=0.33uF
C70 "LMK063BJ224MP-F" 0201_033L 2857.61,5082.34 r180 top value=0.22uF
C71 "LMK063BJ224MP-F" 0201_033L 2857.61,5054.34 r180 top value=0.22uF
C72 "LMK063BJ224MP-F" 0201_033L 3239.31,4941 r180 top value=0.22uF
C73 "C0603X5R1A334K030BC" 0201_033L 3239.52,4912.92 r180 top value=0.33uF
C74 "LMK063BJ224MP-F" 0201_033L 3239.28,4969 r180 top value=0.22uF
C75 "C0603X5R1A334K030BC" 0201_033L 3239.52,4884.92 r180 top value=0.33uF
C76 "C0603X5R1A334K030BC" 0201_033L 2857.55,4912.02 r180 top value=0.33uF
C77 "C0603X5R1A334K030BC" 0201_033L 2857.12,4883.51 r180 top value=0.33uF
C78 "LMK063BJ224MP-F" 0201_033L 2857.61,4968.48 r180 top value=0.22uF
C79 "LMK063BJ224MP-F" 0201_033L 2857.61,4940.34 r180 top value=0.22uF
C80_V1 "GCM188L81H104KA57D" FP-GCM188L81H104KA57D_0603-MFG 3246.21,3559 r90 top (schematic designator C80)
C80_V2 "GCM188L81H104KA57D" FP-GCM188L81H104KA57D_0603-MFG 3247,2390 r90 top (schematic designator C80)
C82_USB1 "GRM033R61A104KE84D" 0201_033L 2853,4672 r0 bottom value=0.1uF (schematic designator C82)
C82_USB2 "GRM033R61A104KE84D" 0201_033L 2809.01,1083.3 r0 bottom value=0.1uF (schematic designator C82)
C83_USB1 "C0603C105K4PACTU" 0603L 2874.55,4713.62 r0 bottom value=1uF (schematic designator C83)
C83_USB2 "C0603C105K4PACTU" 0603L 2828.09,1124.12 r0 bottom value=1uF (schematic designator C83)
C84 "C0603X5R1A334K030BC" 0201_033L 3060.84,4770.17 r90 top value=0.33uF
C85_USB1 "GRM033R61A104KE84D" 0201_033L 2814,4532 r270 bottom value=0.1uF (schematic designator C85)
C85_USB2 "GRM033R61A104KE84D" 0201_033L 2770.01,943.3 r270 bottom value=0.1uF (schematic designator C85)
C86 "GRM188R61E106MA73D" 0603 5118.69,3199.82 r90 top value=10uF
C87 "GRM033R61A104KE84D" 0201_033L 920.63,2992.6 r0 top value=0.1uF
C88_DS1 "CL21B106KOQNNNE" 0805L 5026.77,5000.4 r270 bottom value=10uF (schematic designator C88)
C88_DS2 "CL21B106KOQNNNE" 0805L 5197.95,985 r90 bottom value=10uF (schematic designator C88)
C89 "GRM033R61A104KE84D" 0201_033L 922.47,2764.69 r180 top value=0.1uF
C90 "T520B107M006ATE015" 3528-21 826.6,3665 r180 top value=100uF
C91 "T520B107M006ATE015" 3528-21 825.98,3664.38 r180 bottom value=100uF
C92 "T520B107M006ATE015" 3528-21 853.58,2201.03 r180 top value=100uF
C93 "T520B107M006ATE015" 3528-21 853.18,2052.03 r180 top value=100uF
C94 "GRM21BR61A476ME15L" 0805L 837.54,3778 r180 bottom value=47uF
C95 "GRM21BR61A476ME15L" 0805L 837.54,3778 r180 top value=47uF
C96 "GRM21BR61A476ME15L" 0805L 871.64,1933.03 r180 top value=47uF
C97 "GRM21BR61A476ME15L" 0805L 869.61,1848.03 r180 top value=47uF
C98 "GRM155R60J475ME47D" 0402L 850.57,2752.88 r270 top value=4.7uF
C99 "GRM155R60J475ME47D" 0402L 1026.29,2880.95 r0 top value=4.7uF
C100_USB1 "GRM033R61A104KE84D" 0201_033L 2811.27,4713.62 r90 bottom value=0.1uF (schematic designator C100)
C100_USB2 "GRM033R61A104KE84D" 0201_033L 2767.27,1124.93 r90 bottom value=0.1uF (schematic designator C100)
C101 "EEV-FK1J221Q" SM_RADIAL_H13 311.61,2468.09 r270 top value=220uF
C102 "GCM155R71H104KE02D" 0402L 487,3250 r0 top value=0.1uF
C103 "GRM188R6YA225KA12D" 0603L 158.92,2899.65 r90 top value=2.2uF
C104 "GRM155R6YA105KE11D" 0402L 140.22,3294 r270 top value=1uF
C105 "GRM033Z71C104KE14D" 0201L 3679.56,784.86 r90 top value=0.1uF
C106 "GRM033Z71C104KE14D" 0201L 3690.21,171.05 r270 top value=0.1uF
C107 "GRM033Z71C104KE14D" 0201L 3365.3,439.98 r180 top value=0.1uF
C108 "GRM033Z71C104KE14D" 0201L 3631.33,171.05 r270 top value=0.1uF
C109_US1 "GRM188R6YA475KE15D" 0603L 599,5073 r90 top value=4.7uF (schematic designator C109)
C109_US2 "GRM188R6YA475KE15D" 0603L 633,1547 r90 top value=4.7uF (schematic designator C109)
C110 "GRM033Z71C104KE14D" 0201L 3622,785 r90 top value=0.1uF
C111_US1 "C0402C103J5RACTU" 0402L 430,4643 r0 top value=0.01uF (schematic designator C111)
C111_US2 "C0402C103J5RACTU" 0402L 434,1147 r0 top value=0.01uF (schematic designator C111)
C112 "06035A181JAT2A" 0603L 3990.85,301.56 r270 top value=180pF
C113 "GJM0335C1E100JB01D" 0201L 3996.52,455.34 r270 top value=10pF
C114 "GJM0335C1E100JB01D" 0201L 3996.52,506.64 r90 top value=10pF
C115 "C0402C103J5RACTU" 0402L 4455.86,214.84 r90 top value=0.01uF
C116 "GRM033Z71C104KE14D" 0201L 3277.8,483.26 r90 top value=0.1uF
C118_DS1 "C0402C103J5RACTU" 0402L 5183.85,4848.92 r180 bottom value=0.01uF (schematic designator C118)
C118_DS2 "C0402C103J5RACTU" 0402L 5188.11,1115.2 r180 bottom value=0.01uF (schematic designator C118)
C119_DS1 "C0402C103J5RACTU" 0402L 5090.22,4988.58 r90 bottom value=0.01uF (schematic designator C119)
C119_DS2 "C0402C103J5RACTU" 0402L 5190,1076 r180 bottom value=0.01uF (schematic designator C119)
C120_DS1 "C0402C103J5RACTU" 0402L 5176.21,4520.5 r180 bottom value=0.01uF (schematic designator C120)
C120_DS2 "C0402C103J5RACTU" 0402L 5193,1446 r180 bottom value=0.01uF (schematic designator C120)
C121_DS1 "C0402C103J5RACTU" 0402L 5177.94,4560.51 r180 bottom value=0.01uF (schematic designator C121)
C121_DS2 "C0402C103J5RACTU" 0402L 5192,1407 r180 bottom value=0.01uF (schematic designator C121)
C122_DS1 "GRT188R61H105ME13D" 0603L 4543.49,4570.18 r270 top value=1uF (schematic designator C122)
C122_DS2 "GRT188R61H105ME13D" 0603L 4488.33,1119.81 r180 top value=1uF (schematic designator C122)
C123_DS1 "CGA2B3X7R1H104K050BB" 0402L 4696,4775.71 r270 top value=0.1uF (schematic designator C123)
C123_DS2 "CGA2B3X7R1H104K050BB" 0402L 4673.68,1287.26 r270 top value=0.1uF (schematic designator C123)
C124_US1 "C0402C103J5RACTU" 0402L 410.3,4586.13 r270 top value=0.01uF (schematic designator C124)
C124_US2 "C0402C103J5RACTU" 0402L 414.39,1083.3 r270 top value=0.01uF (schematic designator C124)
C125_US1 "C0402C103J5RACTU" 0402L 553,5063 r90 top value=0.01uF (schematic designator C125)
C125_US2 "C0402C103J5RACTU" 0402L 582,1540 r90 top value=0.01uF (schematic designator C125)
C126_US1 "C0402C103J5RACTU" 0402L 514,5063.64 r90 top value=0.01uF (schematic designator C126)
C126_US2 "C0402C103J5RACTU" 0402L 539,1539 r90 top value=0.01uF (schematic designator C126)
C127 "GRM035R60J475ME15D" 0201L 3660.86,171.05 r270 top value=4.7uF
C128 "GRM035R60J475ME15D" 0201L 3650.03,784.86 r90 top value=4.7uF
C129 "C3216JB1E476M160AC" 1206L 4904.75,2693.4 r90 top value=47uF
C130 "C0402C103J5RACTU" 0402L 5136.46,3904.7 r90 top value=0.01uF
C131 "C0402C103J5RACTU" 0402L 4897.17,2244.94 r270 top value=0.01uF
D1 "150060VS75000" WL-SMCW_GREEN 4978.29,3771.62 r90 top value=Green
D2 "150060VS75000" WL-SMCW_GREEN 4957.96,2015.39 r90 top value=Green
D9 "PESD24VL1BA,115" SOD-323-Bi 509,3185.39 r180 top value=24V
D10 "150060VS75000" WL-SMCW_GREEN 630,3543.96 r270 top value=Green
D11 "150060VS75000" WL-SMCW_GREEN 1082.02,3797.69 r270 top value=Green
D12 "150060VS75000" WL-SMCW_GREEN 882.47,1777.89 r0 top value=Green
D13_DS1 "NSR20F30NXT5G" DSN2_0603 4962,4999.17 r90 bottom value=30V (schematic designator D13)
D13_DS2 "NSR20F30NXT5G" DSN2_0603 5016,1590 r90 bottom value=30V (schematic designator D13)
D14_US1 "NSR20F30NXT5G" DSN2_0603 486,4586 r0 top value=30V (schematic designator D14)
D14_US2 "NSR20F30NXT5G" DSN2_0603 498,1071 r0 top value=30V (schematic designator D14)
D15 "150060VS75000" WL-SMCW_GREEN 4552,3140.77 r270 bottom value=Green
D16 "150060VS75000" WL-SMCW_GREEN 4428.35,3140.88 r270 bottom value=Green
D17 "150060VS75000" WL-SMCW_GREEN 5393.39,4032.77 r270 bottom value=Green
D18 "150060VS75000" WL-SMCW_GREEN 5521.25,4032.08 r270 bottom value=Green
D19 "TPD1E1B04DPYR" DPY0002A 4358.86,165.84 r90 top
D20 "150060VS75000" WL-SMCW_GREEN 4307.86,209.84 r270 top value=Green
D21 "150060VS75000" WL-SMCW_GREEN 5456.79,4032.59 r270 bottom value=Green
FID1 "Fiducial" Fiducial10-20 465,99 r90 top
FID2 "Fiducial" Fiducial10-20 5183.49,5419.29 r90 top
FID3 "Fiducial" Fiducial10-20 443.82,5447 r90 top
FID4 "Fiducial" Fiducial10-20 465,99 r90 bottom
FID5 "Fiducial" Fiducial10-20 443.82,5447 r90 bottom
FID6 "Fiducial" Fiducial10-20 5183.49,5419.29 r90 bottom
H1 "NY PMS 440 0025 PH" "NY PMS 440 0025 PH" 5412.9,201.06 r0 top
H2 "NY PMS 440 0025 PH" "NY PMS 440 0025 PH" 197,197 r0 top
H3 "NY PMS 440 0025 PH" "NY PMS 440 0025 PH" 197,5323 r0 top
H4 "NY PMS 440 0025 PH" "NY PMS 440 0025 PH" 5413,5321 r0 top
J4 "930 176-101" Hirschmann_930_176-101 329,3558 r270 top
J6 "61300411121" WURTH_61300411121 3896.52,886.12 r180 top
J7 "10118193-0001LF" FCI_10118193-0001LF 4659.32,31.46 r0 top
J8_US1 "632723130112" FP-632723130112_CONN_USB_9MM65_10MM0-MFG#1 180,4790 r90 bottom (schematic designator J8)
J8_US2 "632723130112" FP-632723130112_CONN_USB_9MM65_10MM0-MFG#2 180,1294 r90 bottom (schematic designator J8)
J9_DS1 "632723130112" FP-632723130112_CONN_USB_9MM65_10MM0-MFG#2 5434.83,4702.27 r90 top (schematic designator J9)
J9_DS2 "632723130112" FP-632723130112_CONN_USB_9MM65_10MM0-MFG#2 5435.17,1276.76 r90 top (schematic designator J9)
J10 "61301021121" WURTH_61301021121 2952.24,159.26 r0 top
J11 "61000821121" Wurth_61000821121 4400.15,3561.17 r180 top
J13 "61300211121" WURTH_61300211121 4332.85,809.86 r270 top
J14 "61300211121" WURTH_61300211121 4211.08,810.88 r270 top
J15 "930 176-100" Hirschmann_930_176-100 331.92,4061.16 r180 top
L2_DS1 "742792021" 0805L 5188.87,4442.24 r90 bottom value="22 ohm" (schematic designator L2)
L2_DS2 "742792021" 0805L 5081.11,1588 r270 bottom value="22 ohm" (schematic designator L2)
L3_V1 "XAL1010-472MEB" XAL1010 2619.74,3717.88 r0 top value=4.7uH (schematic designator L3)
L3_V2 "XAL1010-472MEB" XAL1010 2623.53,2549.88 r0 top value=4.7uH (schematic designator L3)
L4_USB1 "74279207" 0805L 2871.98,4796.8 r270 bottom value="100 ohm" (schematic designator L4)
L4_USB2 "74279207" 0805L 2803,1208 r270 bottom value="100 ohm" (schematic designator L4)
L5_US1 "742792021" 0805L 448.8,4489 r270 top value="22 ohm" (schematic designator L5)
L5_US2 "742792021" 0805L 473.7,988 r270 top value="22 ohm" (schematic designator L5)
L6 "744314330" WE-HCI_7050 883.65,3402.23 r270 top value=3.3uH
L7 "74279228260" 0603L 4410.17,207.08 r90 top value="26 ohm"
L8 "74437324022" WE-LHMI_4020 910.42,2403.03 r270 top value=2.2uH
Logo1 "Texas Instruments" TI_Stacked_Overlay_Small 1422,396 r0 top
Logo2 "CE Mark" CE_Mark_5mm 1241,535 r180 bottom
Logo4 "WEEE logo" WEEE_Minimum 899,563 r180 bottom
Logo100 "FCC disclaimer" FCC_disclaimer 1424.54,151 r180 bottom
NT1_V1 "Net-Tie" Net-Tie_50milWide_30milLong 2929.19,3835 r90 top net-tie (schematic designator NT1)
NT1_V2 "Net-Tie" Net-Tie_50milWide_30milLong 2932.98,2667 r90 top net-tie (schematic designator NT1)
NT2_USB1 "Net-Tie" Net-Tie_6x8mil 2819.08,4621.62 r180 bottom net-tie (schematic designator NT2)
NT2_USB2 "Net-Tie" Net-Tie_6x8mil 2774.39,1032.55 r180 bottom net-tie (schematic designator NT2)
NT3_USB1 "Net-Tie" Net-Tie_6x8mil 2819.08,4605.87 r180 bottom net-tie (schematic designator NT3)
NT3_USB2 "Net-Tie" Net-Tie_6x8mil 2774.01,1017.17 r180 bottom net-tie (schematic designator NT3)
NT4 "Net-Tie" Net-Tie6milsWide_20milsLong 2885,4370 r0 top net-tie
NT5 "Net-Tie" Net-Tie6milsWide_20milsLong 2885,4382 r0 top net-tie
Q3_V1 "CSD18513Q5A" DQJ0008A 2269.25,3611 r180 top value=40V (schematic designator Q3)
Q3_V2 "CSD18513Q5A" DQJ0008A 2273.04,2419 r180 top value=40V (schematic designator Q3)
Q4_V1 "CSD18513Q5A" DQJ0008A 2488.83,3318.44 r90 top value=40V (schematic designator Q4)
Q4_V2 "CSD18513Q5A" DQJ0008A 2492.62,2150.44 r90 top value=40V (schematic designator Q4)
Q5 "CSD87330Q3D" DQZ0008A 895.11,3145.01 r90 top value=30V
Q6 "CSD87330Q3D" DQZ0008A 889.16,2600.69 r270 top value=30V
Q7 "CSD18513Q5A" DQJ0008A 308.84,2934.55 r270 top value=40V
R1 "CRCW020110K0FKED" 0201L 5027.49,3811.58 r270 top value=10.0k
R2 "CRCW020110K0FKED" 0201L 4993.22,2091.3 r180 top value=10.0k
R3 "CRCW02012K20FKED" 0201L 4714.86,2983.87 r0 bottom value=2.20k
R4 "CRCW02012K20FKED" 0201L 4716.86,3040.87 r0 bottom value=2.20k
R5 "CRCW020110K0FKED" 0201L 4714.86,2955.87 r0 bottom value=10.0k
R6 "CRCW02012K20FKED" 0201L 4714.86,3012.87 r0 bottom value=2.20k
R7 "CRCW02012K20FKED" 0201L 4714.86,2926.87 r0 bottom value=2.20k
R8 "CRCW020110K0FKED" 0201L 4714.86,3068.87 r0 bottom value=10.0k
R9 "CRCW02012K20FKED" 0201L 4775.18,2805.43 r270 top value=2.20k
R10 "CRCW02012K20FKED" 0201L 4746.86,2828.84 r90 top value=2.20k
R11 "CRCW020110K0FKED" 0201L 4714.86,2897.87 r0 bottom value=10.0k
R12 "RC0201FR-07499KL" 0201L 4934.92,3298.22 r270 top value=499k
R13 "RC0201FR-0759KL" 0201L 4903.32,3274.6 r270 top value=59.0k
R14 "CRCW02012K20FKED" 0201L 918.89,3023.72 r0 top value=2.21
R15 "CRCW02012K20FKED" 0201L 896.45,2735.09 r180 top value=2.21
R16 "CRCW020115K4FKED" 0201L 751.7,2907.52 r180 top value=15.4k
R17 "CRCW020110K0FKED" 0201L 4246.22,2867.57 r180 top value=10.0k
R18 "CRCW020110K0FKED" 0201L 4246.22,2777.52 r180 top value=10.0k
R19 "CRCW020110K0FKED" 0201L 4245.73,2725.87 r180 top value=10.0k
R20 "CRCW020110K0FKED" 0201L 4642.73,2807.56 r180 top value=10.0k
R21 "RC0201FR-07499KL" 0201L 4839.86,3231.56 r0 top value=499k
R22 "RC0201FR-0759KL" 0201L 4861,3262 r0 top value=59.0k
R23 "RC0201FR-076K49L" 0201L 751.61,2877.58 r180 top value=6.49k
R24 "CRCW02010000Z0ED" 0201L 841.71,2999.09 r0 top value=0
R25 "CRCW020110K0FKED" 0201L 4246.22,2895.57 r0 top value=10.0k
R26 "CRCW020110K0FKED" 0201L 4246.22,2805.52 r0 top value=10.0k
R27 "CRCW020110K0FKED" 0201L 4246,2697.87 r0 top value=10.0k
R28 "RC0201FR-0751K1L" 0201L 788.77,2980.2 r270 top value=51.1k
R29 "CRCW06030000Z0EA" 0603L 3352.89,593.13 r270 top value=0
R30 "CRCW02010000Z0ED" 0201L 3566.07,195.15 r90 top value=0
R31 "CRCW020110K0FKED" 0201L 4552,2972.06 r270 bottom value=10.0k
R32 "CRCW020110K0FKED" 0201L 4428.35,2978.01 r270 bottom value=10.0k
R33 "CRCW02011K00FKED" 0201L 3214.11,1677.86 r270 bottom value=1.00k
R34 "CRCW02011K00FKED" 0201L 3101.81,1677.32 r270 bottom value=1.00k
R35 "CRCW02011K00FKED" 0201L 3073.26,1677.32 r270 bottom value=1.00k
R36 "CRCW02011K00FKED" 0201L 3270.14,1677.59 r270 bottom value=1.00k
R37 "CRCW020120K0FKED" 0201 3040.18,1593 r180 top
R37 "CRCW02010000Z0ED" 0201L 3242.14,1677.59 r270 bottom value=0
R38 "CRCW02011K00FKED" 0201L 3354.14,1677.59 r270 bottom value=1.00k
R39 "CRCW02011K00FKED" 0201L 3410.14,1677.59 r270 bottom value=1.00k
R40 "CRCW02011K00FKED" 0201L 3186.14,1677.59 r270 bottom value=1.00k
R41 "CRCW02011K00FKED" 0201L 3382.14,1677.59 r270 bottom value=1.00k
R42 "CRCW02011K00FKED" 0201L 3298.14,1677.86 r270 bottom value=1.00k
R43 "CRCW02011K00FKED" 0201L 3158.14,1677.59 r270 bottom value=1.00k
R44 "CRCW02011K00FKED" 0201L 3326.14,1677.59 r270 bottom value=1.00k
R45 "CRCW02010000Z0ED" 0201L 3594,784 r90 top value=0
R46 "CRCW02010000Z0ED" 0201L 3599.04,195.15 r90 top value=0
R47 "CRCW02010000Z0ED" 0201L 3566,783 r90 top value=0
R50 "CRCW02011K00FKED" 0201L 3130.14,1677.59 r270 bottom value=1.00k
R51 "CRCW020120K0FKED" 0201L 3214.11,1771.69 r270 bottom value=20.0k
R52 "CRCW020120K0FKED" 0201L 3102.14,1771.59 r270 bottom value=20.0k
R53 "CRCW020120K0FKED" 0201L 3073.26,1771.42 r270 bottom value=20.0k
R54 "CRCW02010000Z0ED" 0201 3268.21,1681.49 r90 top
R54 "CRCW02010000Z0ED" 0201L 3270.14,1771.86 r270 bottom value=0
R55 "CRCW020120K0FKED" 0201L 3242.14,1771.86 r270 bottom value=20.0k
R56 "CRCW02010000Z0ED" 0201 3353,1683 r90 top
R56 "CRCW02010000Z0ED" 0201L 3354.14,1770.59 r270 bottom value=0
R57 "CRCW02010000Z0ED" 0201 3410.14,1781.62 r270 top
R57 "CRCW02010000Z0ED" 0201L 3410.14,1770.59 r270 bottom value=0
R58 "CRCW020120K0FKED" 0201L 3186.14,1771.61 r270 bottom value=20.0k
R59 "CRCW02010000Z0ED" 0201 3382.07,1782.71 r270 top
R59 "CRCW02010000Z0ED" 0201L 3382.14,1771.61 r270 bottom value=0
R60 "CRCW02010000Z0ED" 0201 3297,1682 r90 top
R60 "CRCW02010000Z0ED" 0201L 3298.14,1770.86 r270 bottom value=0
R61 "CRCW02010000Z0ED" 0201 3040,1621 r0 top
R61 "CRCW02010000Z0ED" 0201L 3158.14,1771.59 r270 bottom value=0
R63 "RC0201FR-7D1ML" 0201L 5016,3897 r180 top value=1.00Meg
R64 "RC0201FR-7D124KL" 0201L 4962.33,3896.96 r0 top value=51.0k
R65_V1 "RC0201FR-071RL" 0201 2640.9,3208.4 r180 top value=1.00 (schematic designator R65)
R65_V2 "RC0201FR-071RL" 0201 2644.68,2040.4 r180 top value=1.00 (schematic designator R65)
R67_V1 "RC0201FR-071RL" 0201 2378.79,3762.18 r270 top value=1.00 (schematic designator R67)
R67_V2 "RC0201FR-071RL" 0201 2382.08,2569.6 r270 top value=1.00 (schematic designator R67)
R68_V1 "RC0201FR-07147KL" 0201L 3093.17,3296.99 r90 top value=147k (schematic designator R68)
R68_V2 "RC0201FR-07147KL" 0201L 3096.96,2128.99 r90 top value=147k (schematic designator R68)
R69_V1 "CRF1206-FZ-R010ELF" FP-CRF1206-FZ-R010ELF_1206-MFG 3362.94,3815.9 r0 top (schematic designator R69)
R69_V2 "CRF1206-FZ-R010ELF" FP-CRF1206-FZ-R010ELF_1206-MFG 3366.73,2647.9 r0 top (schematic designator R69)
R70_V1 "RC0201FR-07115KL" 0201L 3134.39,3285.96 r180 top value=115k (schematic designator R70)
R70_V2 "RC0201FR-07115KL" 0201L 3138.18,2117.96 r180 top value=115k (schematic designator R70)
R71_V1 "RC0201FR-07102KL" 0201L 3184.46,3970.84 r90 top value=102k (schematic designator R71)
R71_V2 "RC0201FR-07102KL" 0201L 3185.54,2803 r90 top value=102k (schematic designator R71)
R72_V1 "RC0201FS-7D10RL" 0201L 3220.35,3816.43 r0 top value=10.0 (schematic designator R72)
R72_V2 "RC0201FS-7D10RL" 0201L 3224.14,2648.43 r0 top value=10.0 (schematic designator R72)
R73_V1 "RC0201FR-7D49K9L" 0201L 3226.92,3310 r90 top value=49.9k (schematic designator R73)
R73_V2 "RC0201FR-7D49K9L" 0201L 3230.71,2142 r90 top value=49.9k (schematic designator R73)
R74_V1 "RC0201FR-0756K2L" 0201L 3041.28,3882.51 r0 top value=56.2k (schematic designator R74)
R74_V2 "RC0201FR-0756K2L" 0201L 3045.06,2714.51 r0 top value=56.2k (schematic designator R74)
R75_V1 "RC0201FR-7D6K19L" 0201L 3155,3971.5 r270 top value=6.19k (schematic designator R75)
R75_V2 "RC0201FR-7D6K19L" 0201L 3156.5,2803.5 r270 top value=6.19k (schematic designator R75)
R76_V1 "RC0201FR-07150KL" 0201L 3122.27,3971.36 r270 top value=150k (schematic designator R76)
R76_V2 "RC0201FR-07150KL" 0201L 3126.06,2803.36 r270 top value=150k (schematic designator R76)
R77_V1 "RC0201FS-7D10RL" 0201L 3282.73,3913.88 r270 top value=10.0 (schematic designator R77)
R77_V2 "RC0201FS-7D10RL" 0201L 3286.51,2745.88 r270 top value=10.0 (schematic designator R77)
R78 "CRCW02011K00FKED" 0201L 3191.31,4803 r270 top value=1.00k
R79 "CRCW02011K00FKED" 0201L 2977.65,5346.34 r90 bottom value=1.00k
R80 "CRCW02011K00FKED" 0201L 2891.67,5346.34 r90 bottom value=1.00k
R81 "CRCW02011K00FKED" 0201L 3092.29,5346.66 r90 bottom value=1.00k
R82 "CRCW02011K00FKED" 0201L 3034.97,5346.34 r90 bottom value=1.00k
R83 "CRCW02011K00FKED" 0201L 3120.95,5346.66 r90 bottom value=1.00k
R84 "CRCW02011K00FKED" 0201L 3063.63,5346.66 r90 bottom value=1.00k
R85 "CRCW02011K00FKED" 0201L 2948.99,5346.34 r90 bottom value=1.00k
R86 "CRCW02011K00FKED" 0201L 3006.31,5346.34 r90 bottom value=1.00k
R87 "CRCW02011K00FKED" 0201L 2920.33,5346.66 r90 bottom value=1.00k
R90_USB1 "RC0201FR-073K65L" 0201L 2757.5,4531.62 r270 bottom value=3.65k (schematic designator R90)
R90_USB2 "RC0201FR-073K65L" 0201L 2713.5,942.92 r270 bottom value=3.65k (schematic designator R90)
R91_USB1 "RC0201FR-071K82L" 0201L 2786,4532 r270 bottom value=1.82k (schematic designator R91)
R91_USB2 "RC0201FR-071K82L" 0201L 2742.01,943.3 r270 bottom value=1.82k (schematic designator R91)
R92 "CRCW020110K0FKED" 0201L 5497,3828.46 r270 bottom value=10.0k
R93 "CRCW020120K0FKED" 0201L 2977.28,5251.66 r90 bottom value=20.0k
R94 "CRCW020120K0FKED" 0201L 2891.67,5251.67 r90 bottom value=20.0k
R95 "CRCW020120K0FKED" 0201L 3091.42,5253.66 r90 bottom value=20.0k
R96 "CRCW020120K0FKED" 0201L 3034.35,5251.66 r90 bottom value=20.0k
R97 "CRCW020120K0FKED" 0201L 3119.95,5253.66 r90 bottom value=20.0k
R98 "CRCW020120K0FKED" 0201L 3062.88,5251.66 r90 bottom value=20.0k
R99 "CRCW020120K0FKED" 0201L 2948.74,5251.67 r90 bottom value=20.0k
R100 "CRCW020120K0FKED" 0201L 3005.81,5251.66 r90 bottom value=20.0k
R101 "CRCW020120K0FKED" 0201L 2920.21,5251.67 r90 bottom value=20.0k
R102 "CRCW020110K0FKED" 0201L 4458.22,3066.63 r90 bottom value=10.0k
R103_USB1 "RC0201FR-0712K4L" 0201L 2783.27,4713.62 r270 bottom value=12.4k (schematic designator R103)
R103_USB2 "RC0201FR-0712K4L" 0201L 2730.93,1124.93 r270 bottom value=12.4k (schematic designator R103)
R104_USB1 "RC0201FR-0727K4L" 0201L 2755,4714 r270 bottom value=27.4k (schematic designator R104)
R104_USB2 "RC0201FR-0727K4L" 0201L 2691.92,1124.93 r270 bottom value=27.4k (schematic designator R104)
R105 "RC0201FR-072ML" 0201L 4906.58,4050.1 r90 top value=2.00Meg
R106 "CRCW020110K0FKED" 0201L 4905,3970 r90 top value=10.0k
R107 "RC0201FR-07931KL" 0201L 4895.58,4010.1 r180 top value=51.0k
R108 "CRCW02010000Z0ED" 0201L 4803.6,2805.22 r90 top value=0
R109 "CRCW02010000Z0ED" 0201L 4757.86,2869.87 r0 top value=0
R110 "RC0201FR-07470RL" 0201L 4551.61,3060.54 r270 bottom value=470
R111 "CRCW020110K0FKED" 0201L 751.61,2849.03 r0 top value=10.0k
R112 "CRCW020110K0FKED" 0201L 751.7,2936.06 r0 top value=10.0k
R113 "RC0201FR-7D47K5L" 0201L 775.83,2792.17 r90 top value=47.5k
R114 "RC0201FR-071K69L" 0201L 630,3449 r270 top value=1.69k
R115 "RC0201FR-07715RL" 0201L 1014.48,3764.22 r180 top value=715
R116 "RC0201FR-07470RL" 0201L 961,1803 r90 top value=470
R117_V1 "RC0201FR-0742K2L" 0201L 3089.37,3971.36 r270 top value=42.2k (schematic designator R117)
R117_V2 "RC0201FR-0742K2L" 0201L 3093.16,2803.36 r270 top value=42.2k (schematic designator R117)
R118 "RC0201FR-07470RL" 0201L 4428.35,3067.19 r270 bottom value=470
R123 "CRCW020120K0FKED" 0201L 3326.14,1771.59 r270 bottom value=20.0k
R124 "CRCW020120K0FKED" 0201L 3130.14,1771.42 r270 bottom value=20.0k
R125 "CRCW020110K0FKED" 0201L 3782.39,778.37 r0 top value=10.0k
R126 "CRCW020110K0FKED" 0201L 3731.85,772.86 r180 top value=10.0k
R127 "CRCW040210K0JNED" 0402L 3965.32,372.07 r0 top value=10k
R128 "CRCW02010000Z0ED" 0201L 5497,3916.09 r270 bottom value=0
R129 "CRCW02010000Z0ED" 0201L 4458.22,2978.06 r90 bottom value=0
R130 "CRCW020110K0FKED" 0201L 4517.7,3063.85 r90 bottom value=10.0k
R131 "CRCW020110K0FKED" 0201L 4487.98,3067.18 r90 bottom value=10.0k
R132 "CRCW02010000Z0ED" 0201L 4837.31,2737.98 r270 top value=0
R133 "CRCW02010000Z0ED" 0201L 4773.08,2738.39 r270 top value=0
R134 "RC0201FR-07715RL" 0201 4362.92,254.32 r270 top value=715
R135 "CRCW02010000Z0ED" 0201L 5390.72,3916.09 r270 bottom value=0
R136 "CRCW020110K0FKED" 0201L 5390.24,3828.46 r270 bottom value=10.0k
R137 "CRCW020110K0FKED" 0201L 5419.28,3828.46 r270 bottom value=10.0k
R138 "CRCW020110K0FKED" 0201L 5526.89,3828.46 r270 bottom value=10.0k
R139 "CRCW02010000Z0ED" 0201L 5107.68,3999.76 r180 top value=0
R140 "CRCW02010000Z0ED" 0201L 3089.61,4769.69 r270 top value=0
R144_USB1 "CRCW02010000Z0ED" 0201L 2841.98,4531.62 r270 bottom value=0 (schematic designator R144)
R144_USB2 "CRCW02010000Z0ED" 0201L 2797.98,942.92 r270 bottom value=0 (schematic designator R144)
R145_USB1 "CRCW02010000Z0ED" 0201L 2869.95,4532 r270 bottom value=0 (schematic designator R145)
R145_USB2 "CRCW02010000Z0ED" 0201L 2825.96,943.3 r270 bottom value=0 (schematic designator R145)
R146 "CRCW02010000Z0ED" 0201L 4805.82,2738.41 r270 top value=0
R147 "CRCW02010000Z0ED" 0201L 4518.35,2974.85 r90 bottom value=0
R148 "CRCW02010000Z0ED" 0201L 4487.22,2978.18 r90 bottom value=0
R149 "CRCW02010000Z0ED" 0201L 2947.17,1187.74 r180 top value=0
R150 "CRCW02010000Z0ED" 0201L 2958.17,1147.74 r270 top value=0
R151 "CRCW02010000Z0ED" 0201L 3012.31,1147.74 r270 top value=0
R152 "CRCW02010000Z0ED" 0201L 3002.17,1187.74 r180 top value=0
R153 "CRCW02010000Z0ED" 0201L 2991.45,4769.33 r270 top value=0
R154 "CRCW02010000Z0ED" 0201L 2963.31,4769 r270 top value=0
R155 "CRCW02010000Z0ED" 0201L 3183.51,365.57 r270 top value=0
R156 "RC0201FR-07470RL" 0201L 5420,3916.09 r270 bottom value=470
R157 "CRCW02010000Z0ED" 0201L 3211.85,365.57 r270 top value=0
R158 "RC0201FR-07470RL" 0201L 5526.89,3916.09 r270 bottom value=470
R159_DS1 "CRCW02010000Z0ED" 0201L 4682.22,4446.75 r90 top value=0 (schematic designator R159)
R159_DS2 "CRCW02010000Z0ED" 0201L 4659.9,981.59 r90 top value=0 (schematic designator R159)
R160_DS1 "CRCW02010000Z0ED" 0201L 4640.83,4447.27 r90 top value=0 (schematic designator R160)
R160_DS2 "CRCW02010000Z0ED" 0201L 4618.56,980.61 r90 top value=0 (schematic designator R160)
R161 "CRCW02010000Z0ED" 0201L 3231.09,301.56 r180 top value=0
R162 "CRCW020110K0FKED" 0201L 3239.85,365.57 r90 top value=10.0k
R163_DS1 "CRCW0201100KFKED" 0201L 4597.08,4607.78 r90 top value=100k (schematic designator R163)
R163_DS2 "CRCW0201100KFKED" 0201L 4554.97,1138.51 r90 top value=100k (schematic designator R163)
R164 "CRCW0201100RFKED" 0201L 5123.6,3960.2 r0 top value=100
R165 "CRCW020110K0FKED" 0201L 5464.66,3828.46 r270 bottom value=10.0k
R166 "RC0201FR-7D1ML" 0201L 5086.26,2238.45 r270 top value=1.00Meg
R167 "RC0201FR-7D124KL" 0201L 5127.26,2226.45 r180 top value=51.0k
R168 "RC0201FR-072ML" 0201L 5115.27,2106.3 r270 top value=2.00Meg
R169 "CRCW020110K0FKED" 0201L 5115.27,2182.81 r270 top value=10.0k
R170 "RC0201FR-07931KL" 0201L 5127.08,2144.45 r0 top value=51.0k
R171 "CRCW02010000Z0ED" 0201L 4927.15,2127.55 r0 top value=0
R172 "CRCW0201100RFKED" 0201L 4907.52,2189.07 r180 top value=100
